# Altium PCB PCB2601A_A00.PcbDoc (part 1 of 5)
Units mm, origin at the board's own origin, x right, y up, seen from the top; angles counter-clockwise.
Board outline 30.4 x 51 mm, 8 copper layers (Top Layer, Signal Layer 2, Signal Layer 3, Signal Layer 4, Signal Layer 5, Signal Layer 6, Signal Layer 7, Bottom Layer), stack 1.492 mm thick; 194 components, 130 nets, 5039 pads, 478 vias.
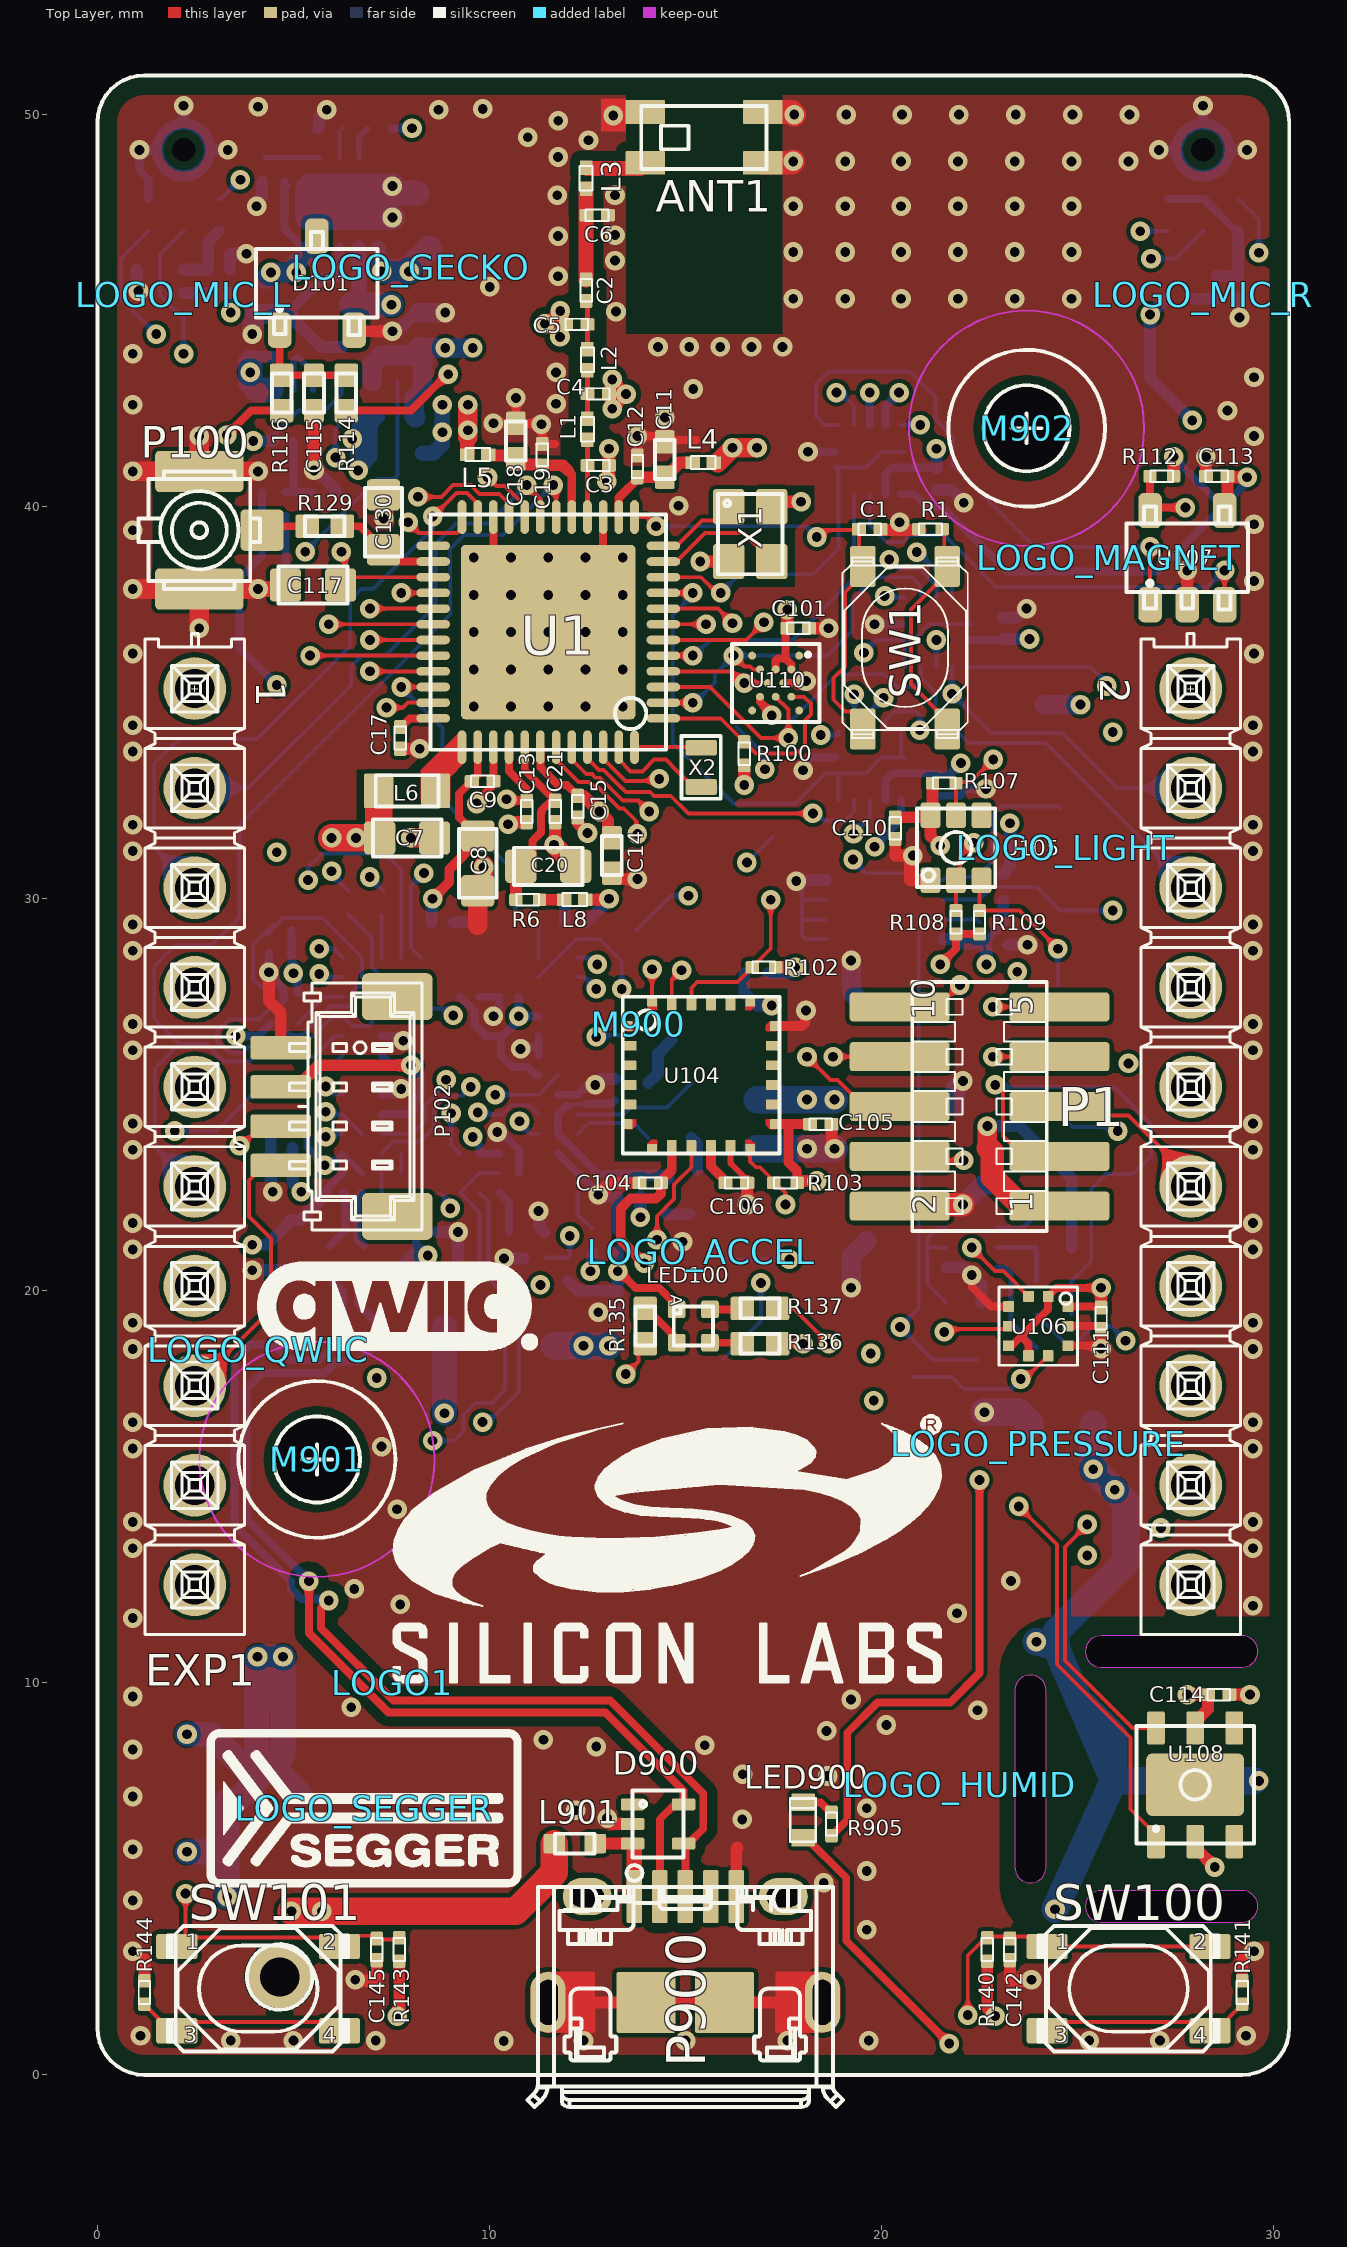
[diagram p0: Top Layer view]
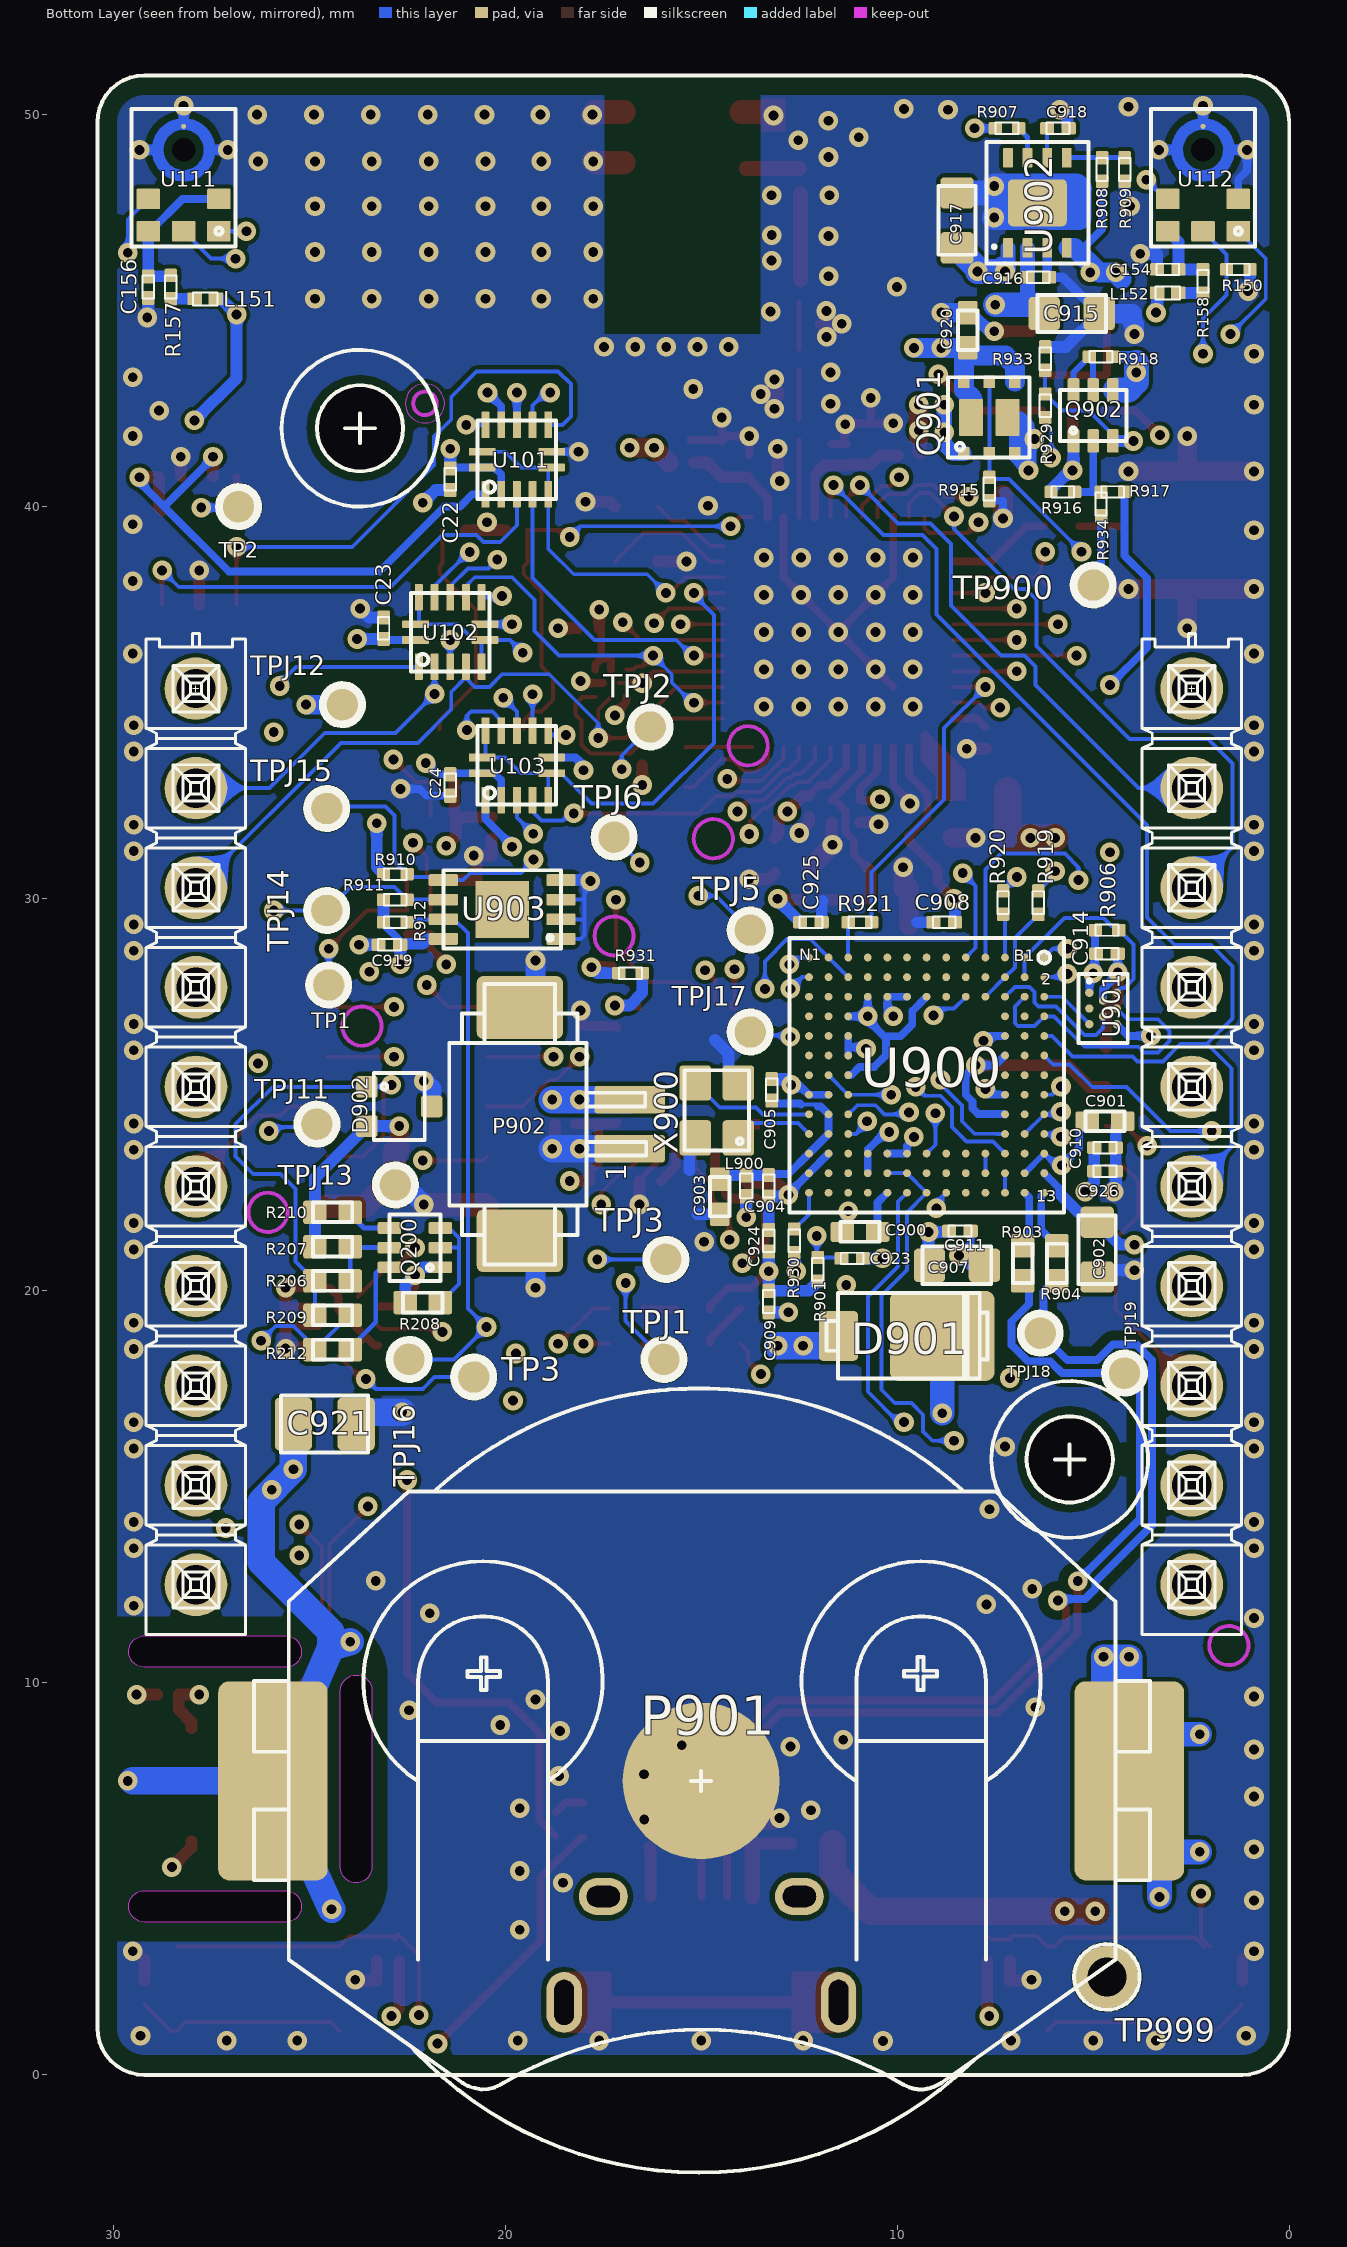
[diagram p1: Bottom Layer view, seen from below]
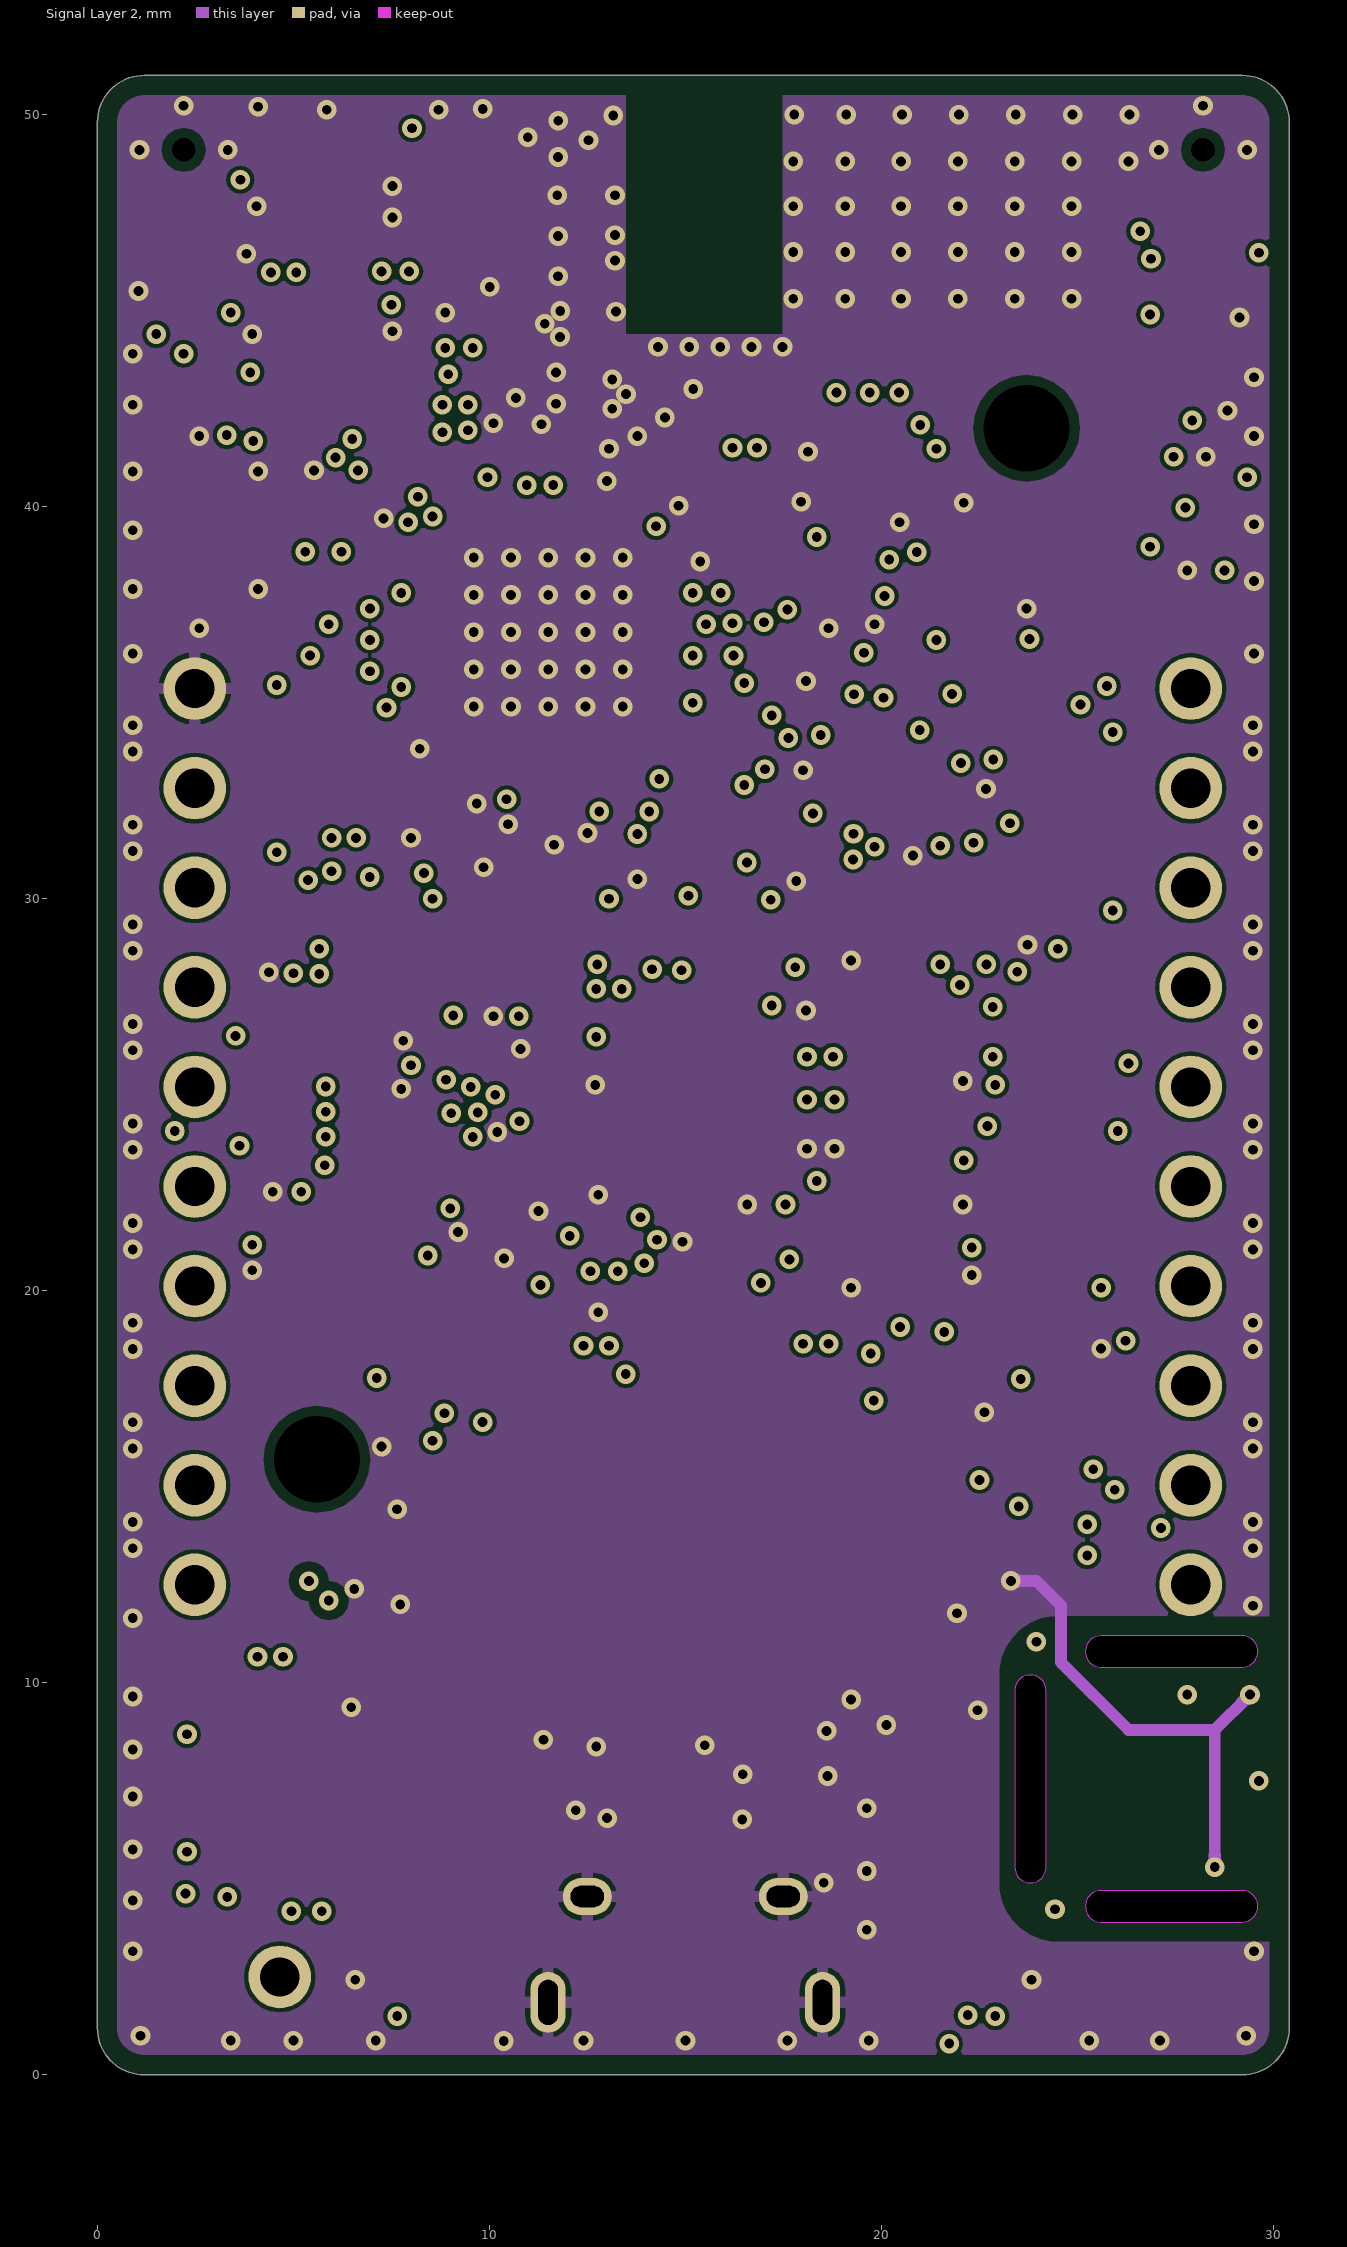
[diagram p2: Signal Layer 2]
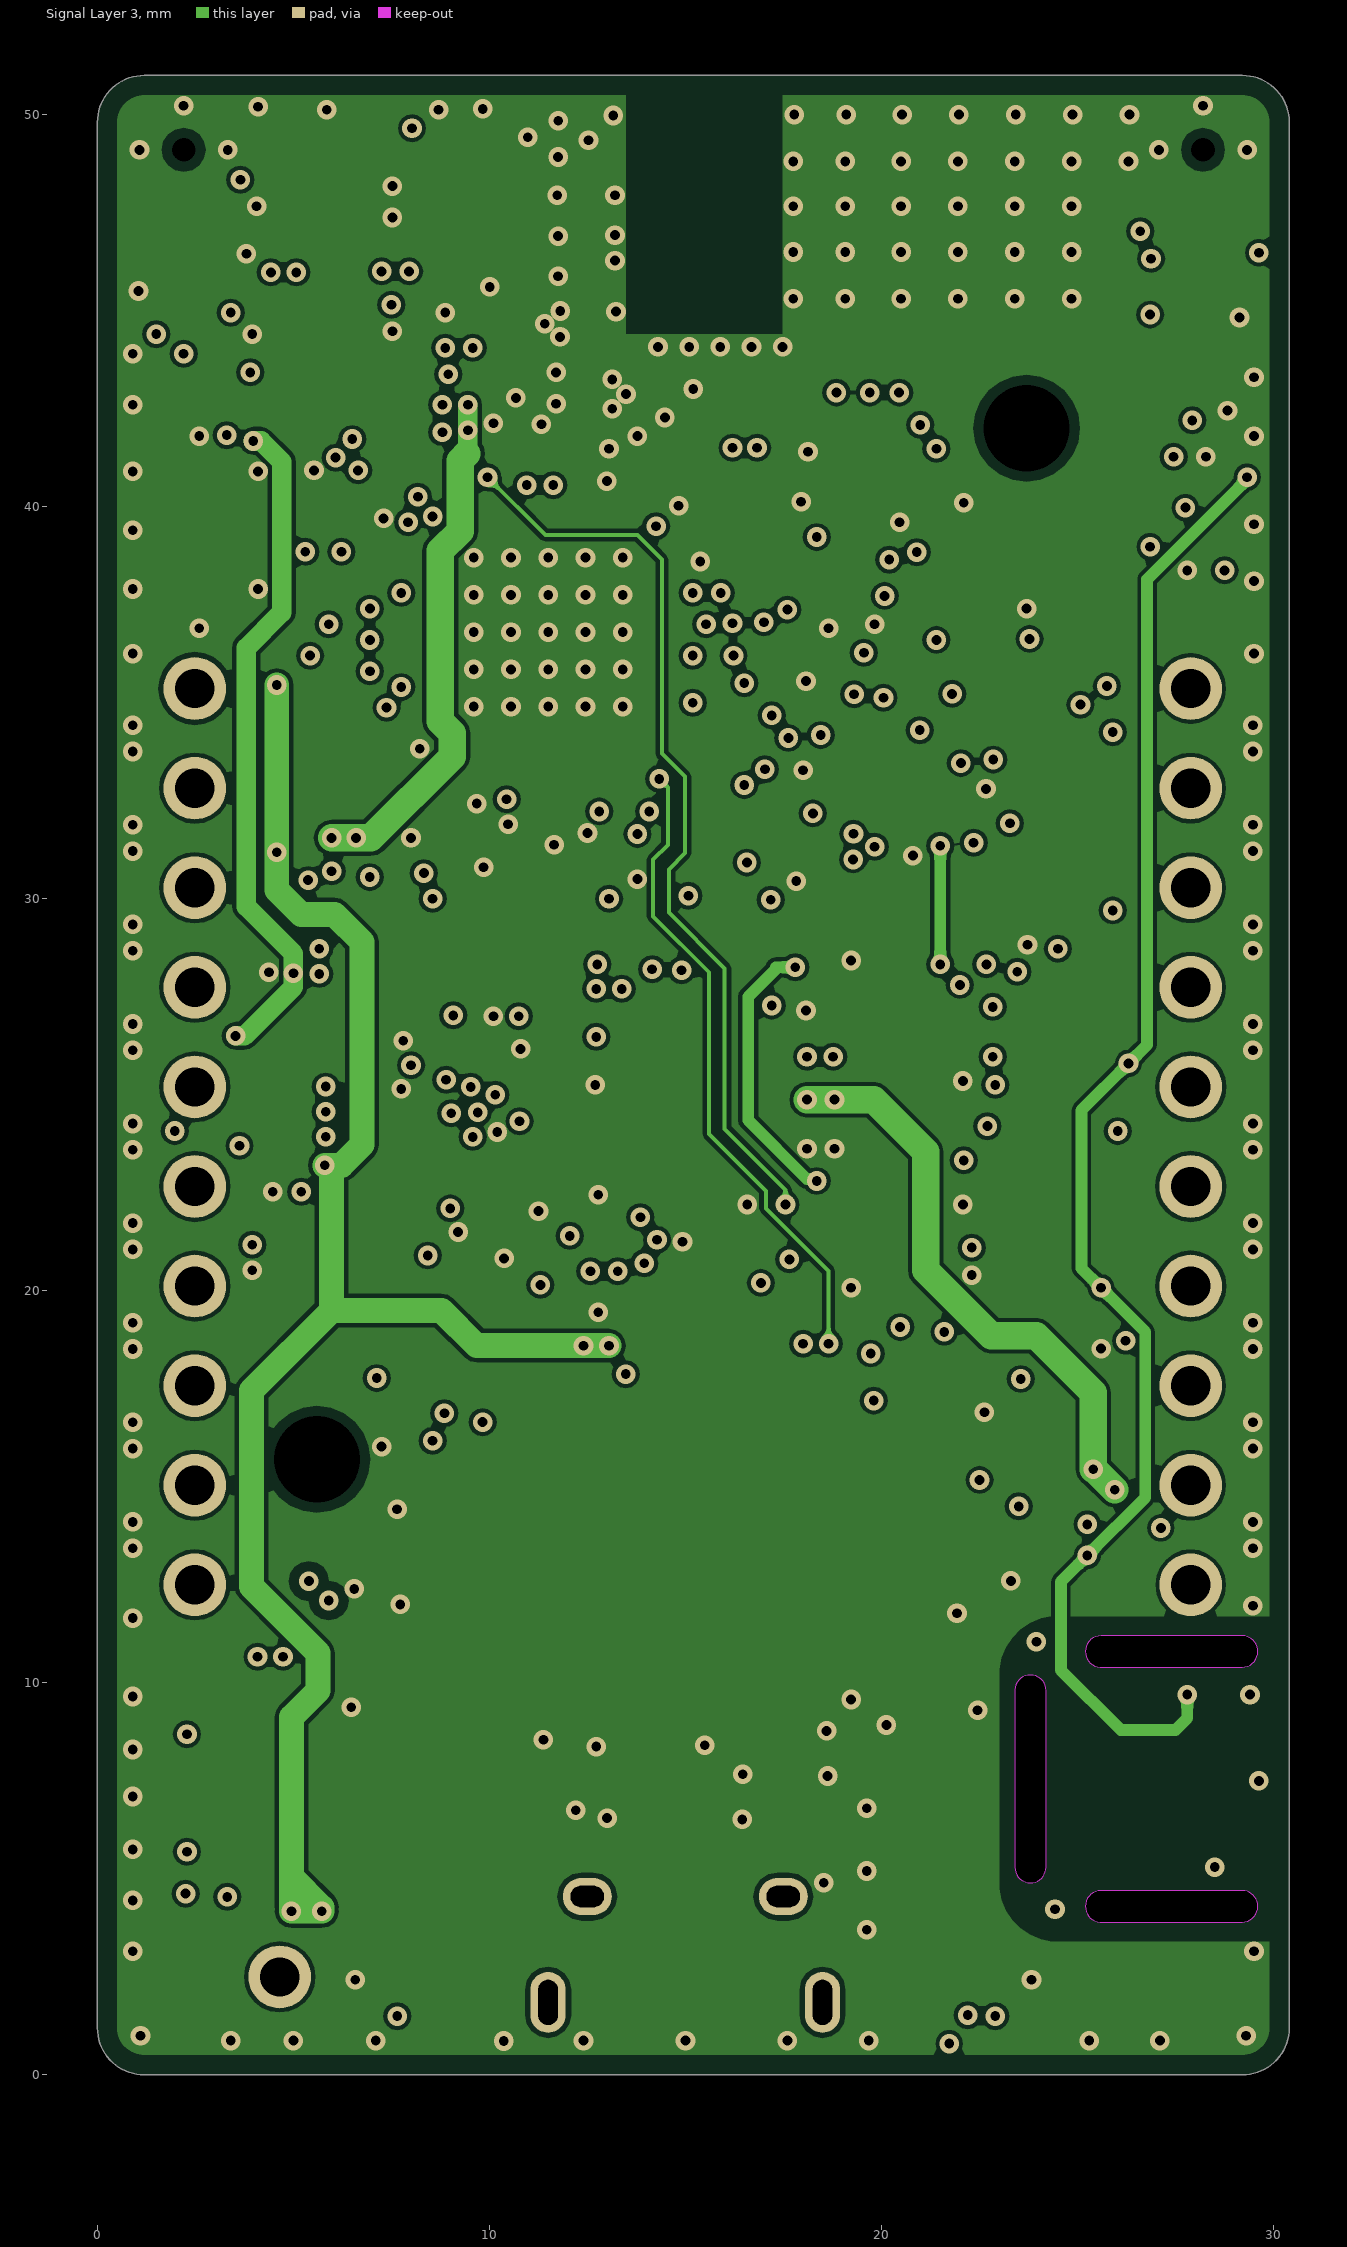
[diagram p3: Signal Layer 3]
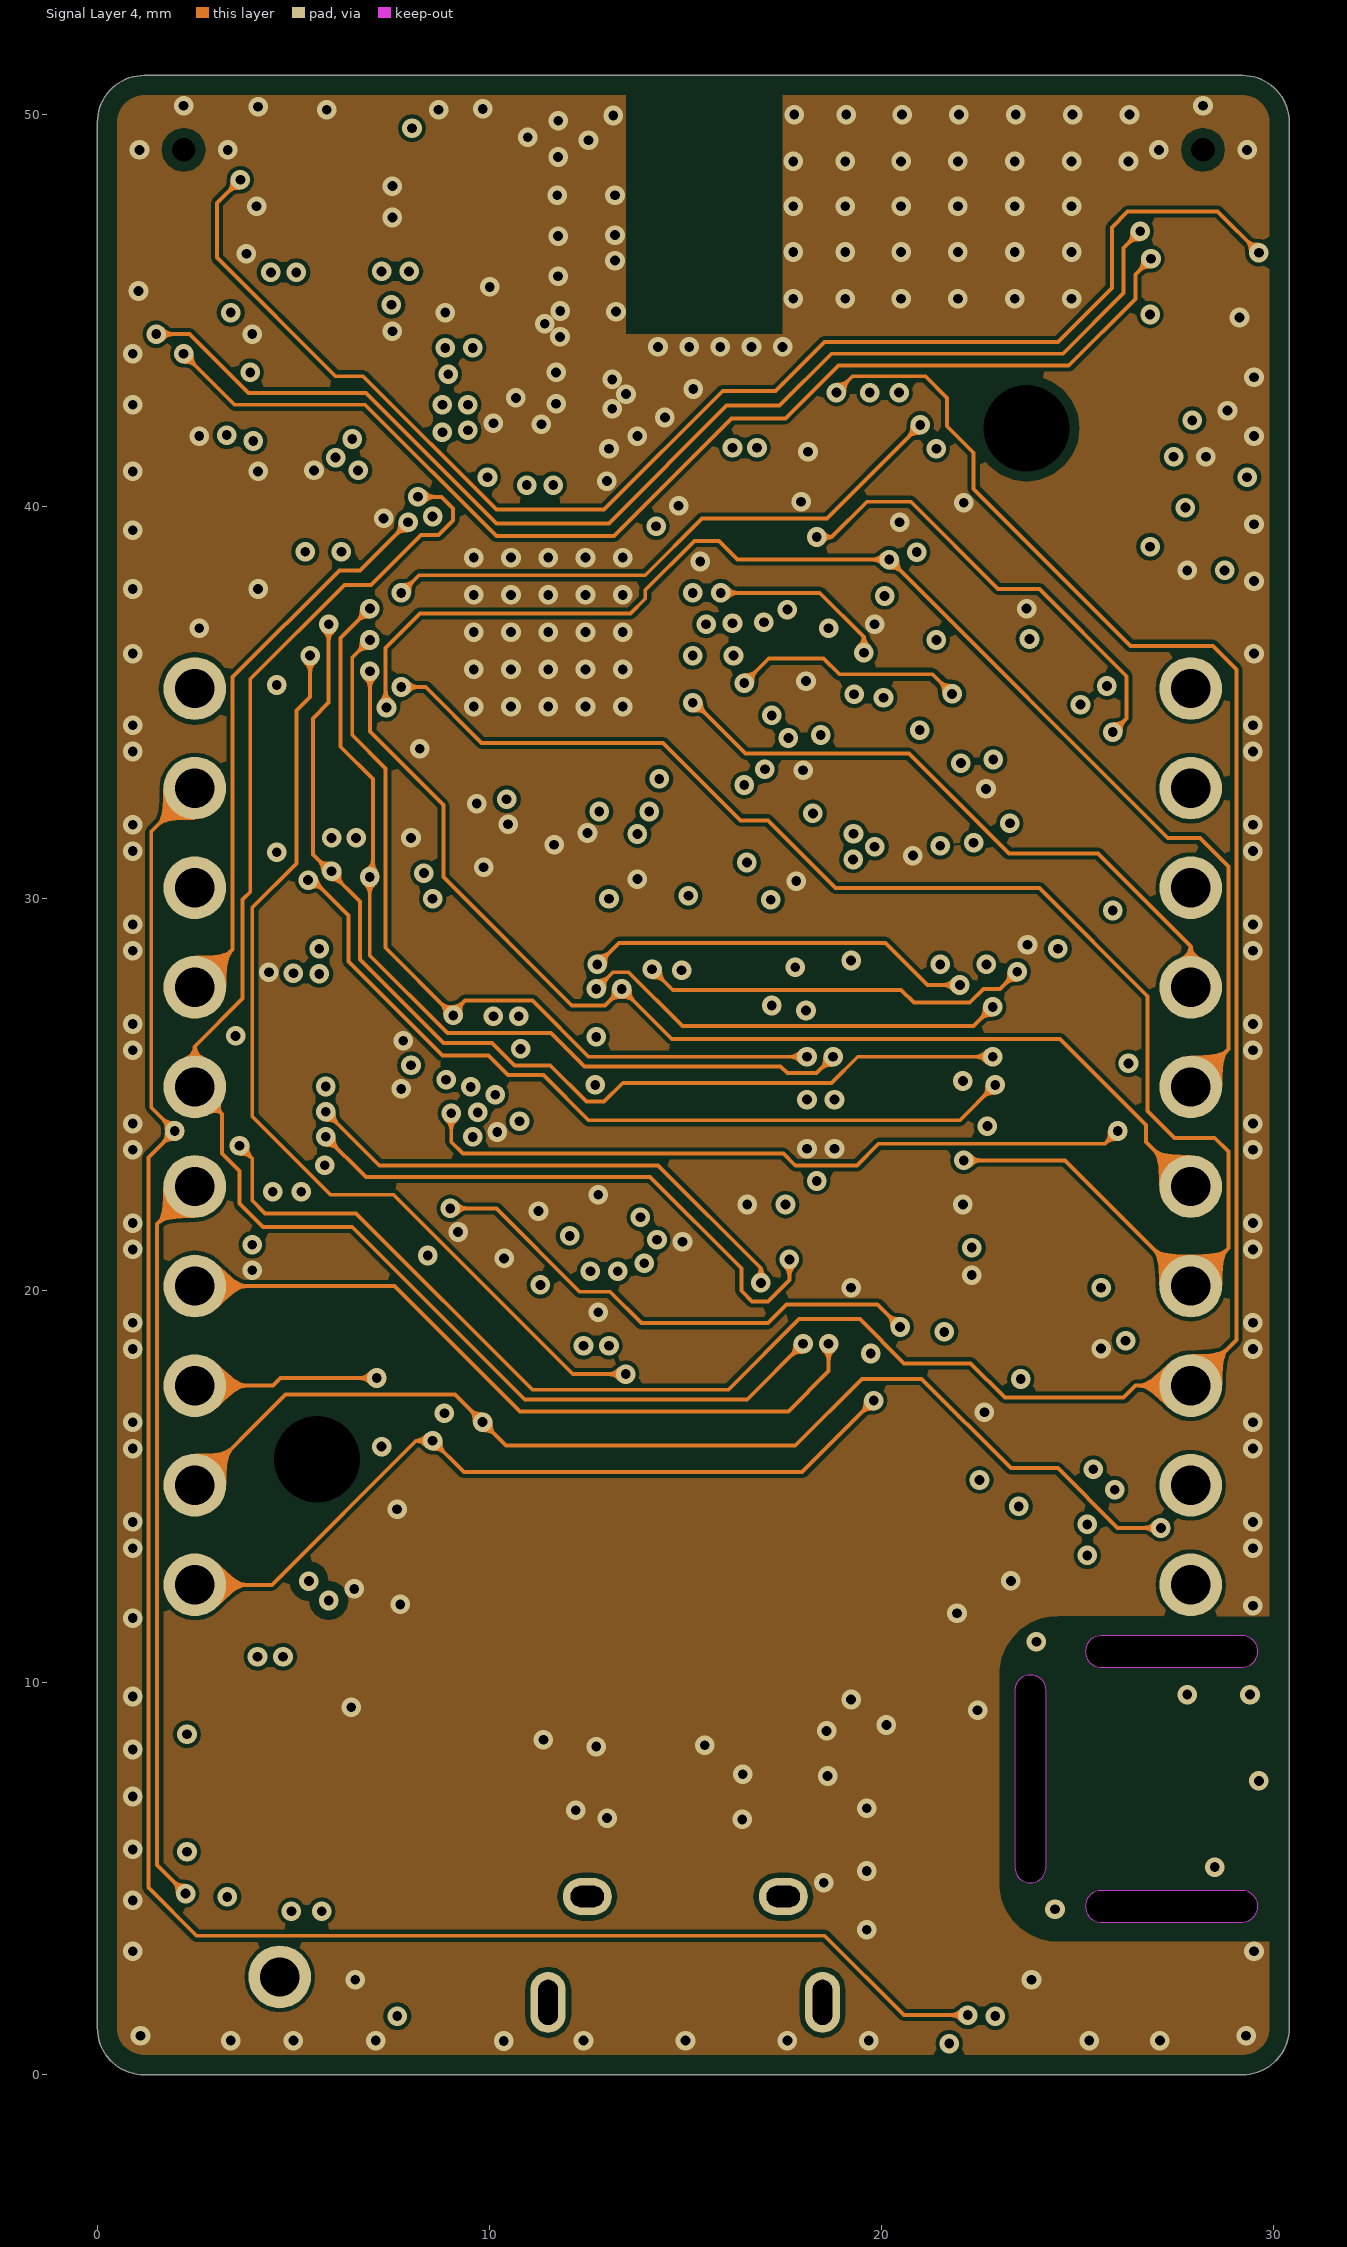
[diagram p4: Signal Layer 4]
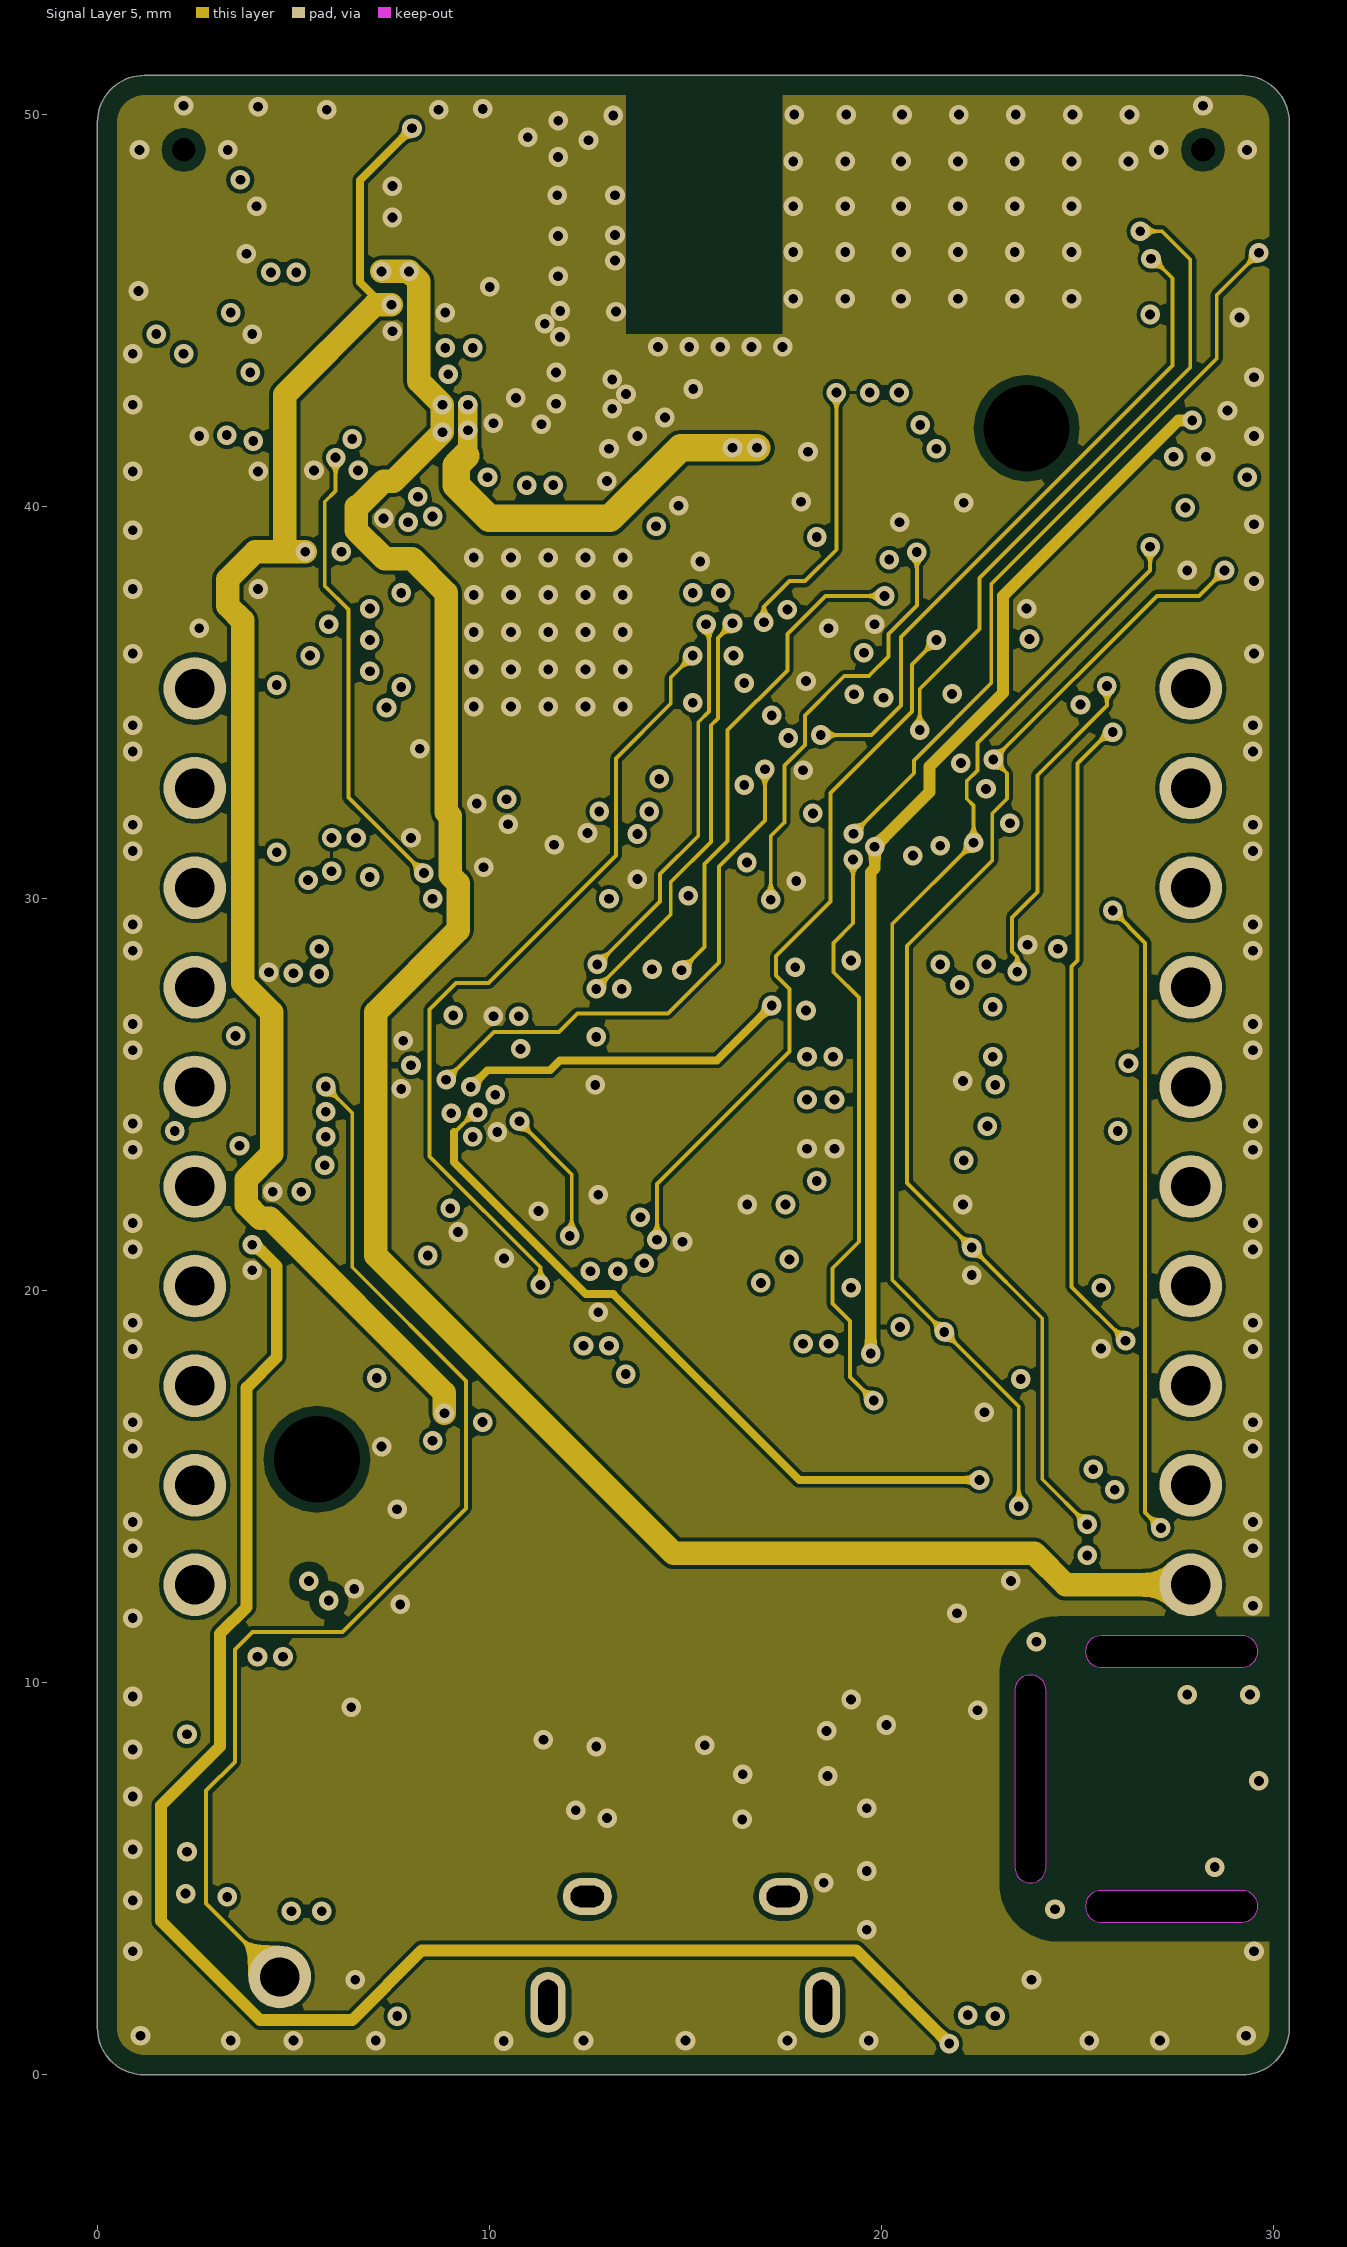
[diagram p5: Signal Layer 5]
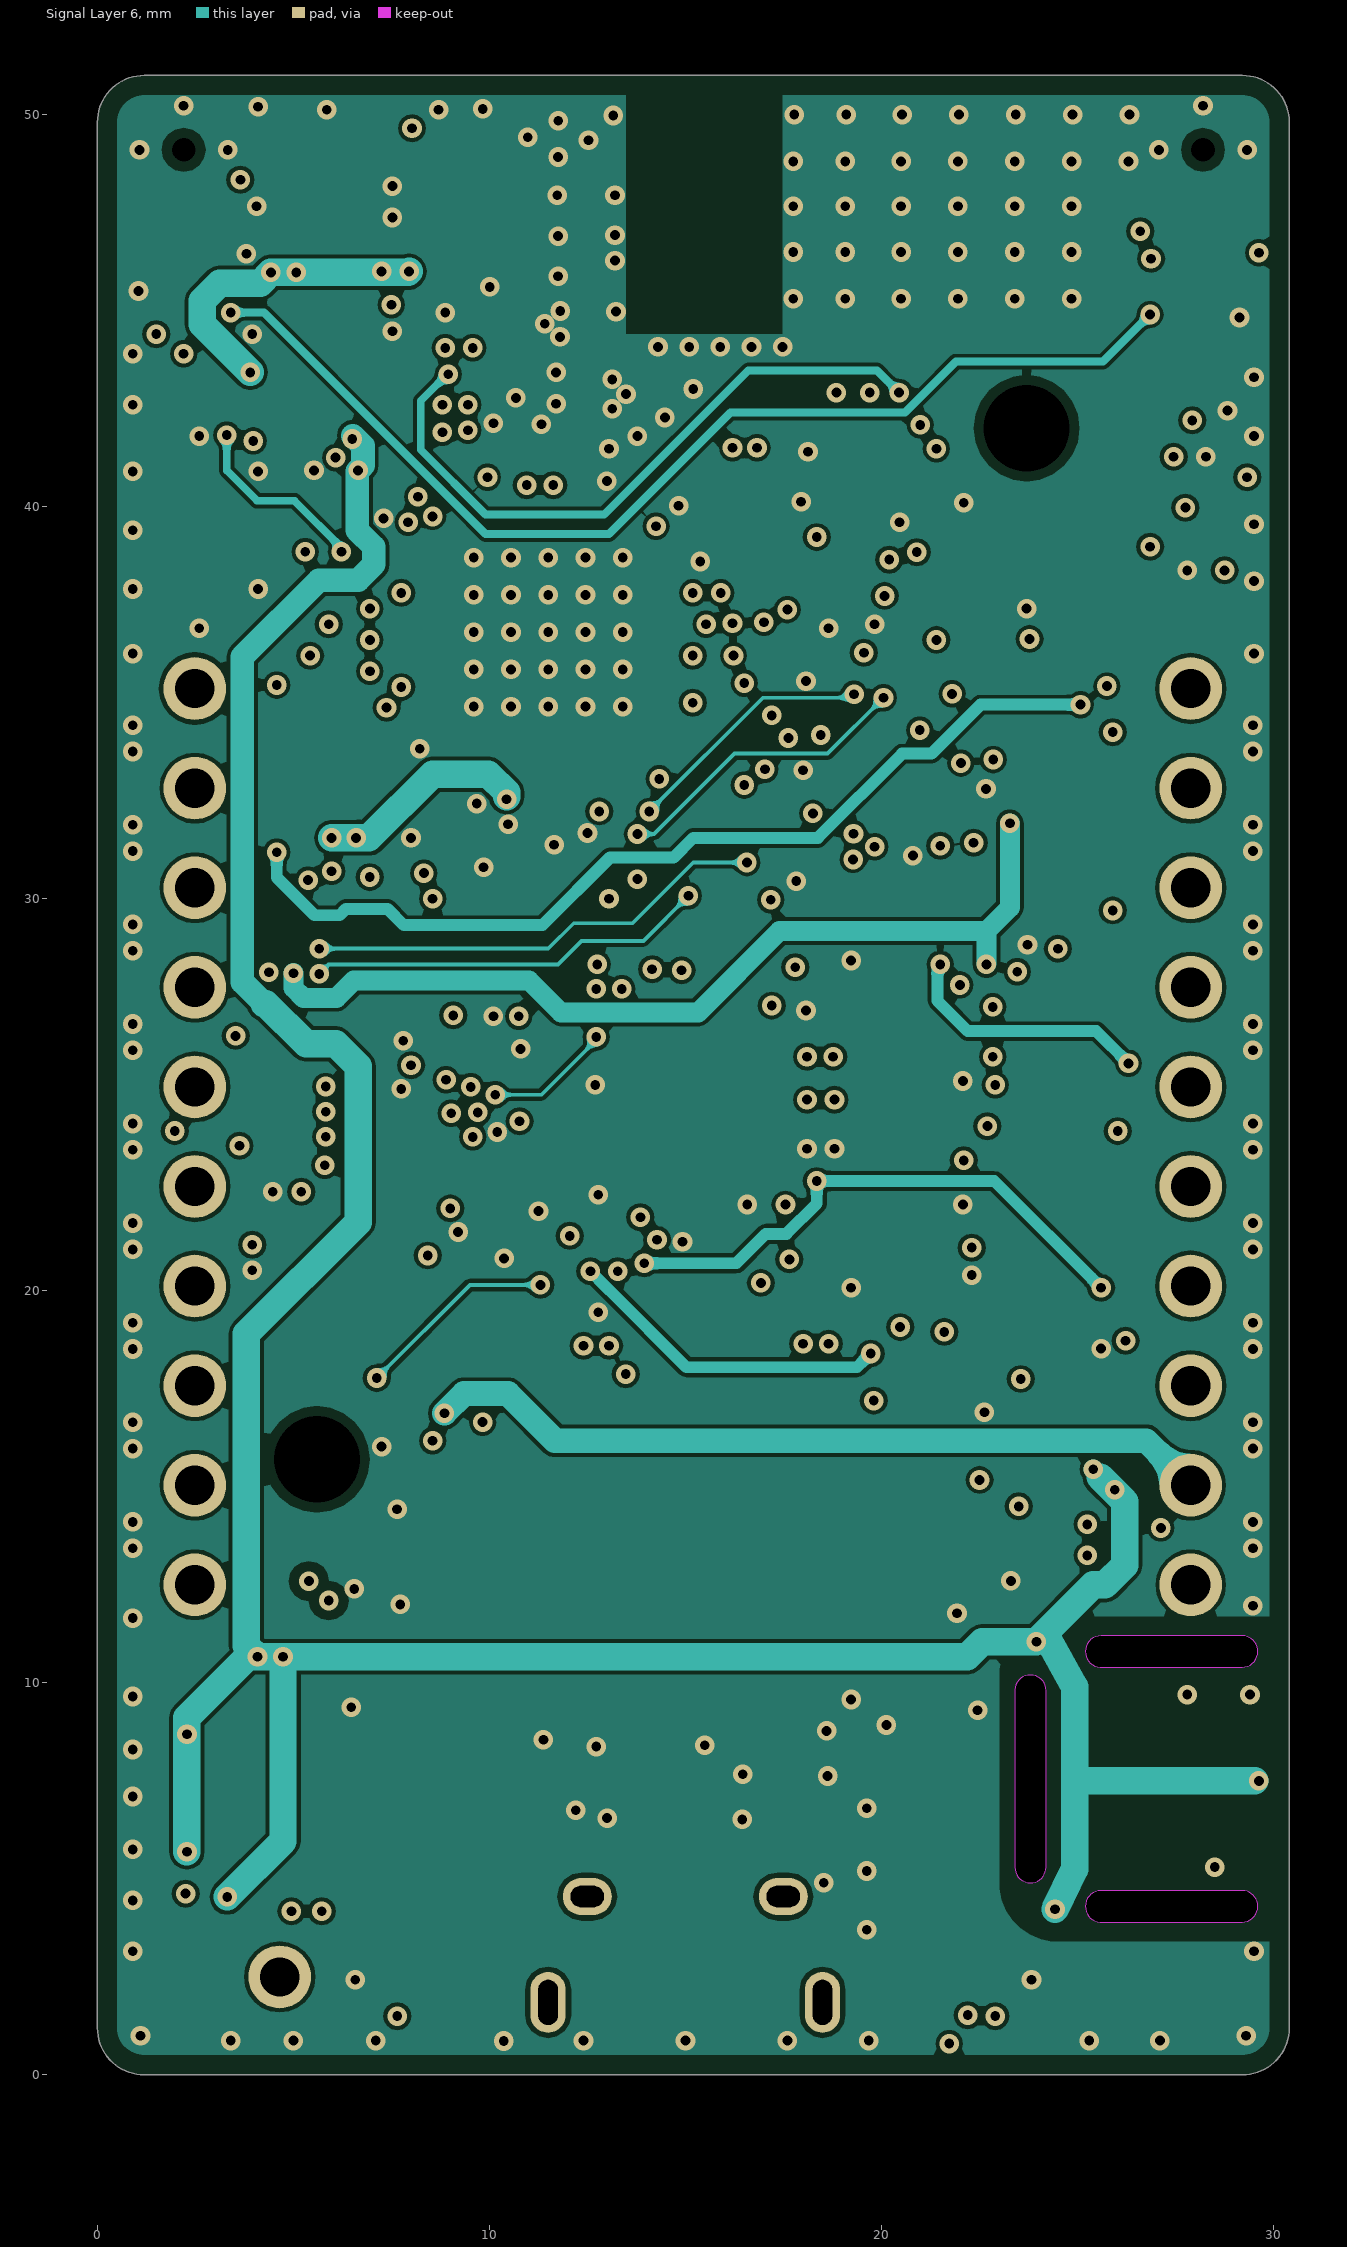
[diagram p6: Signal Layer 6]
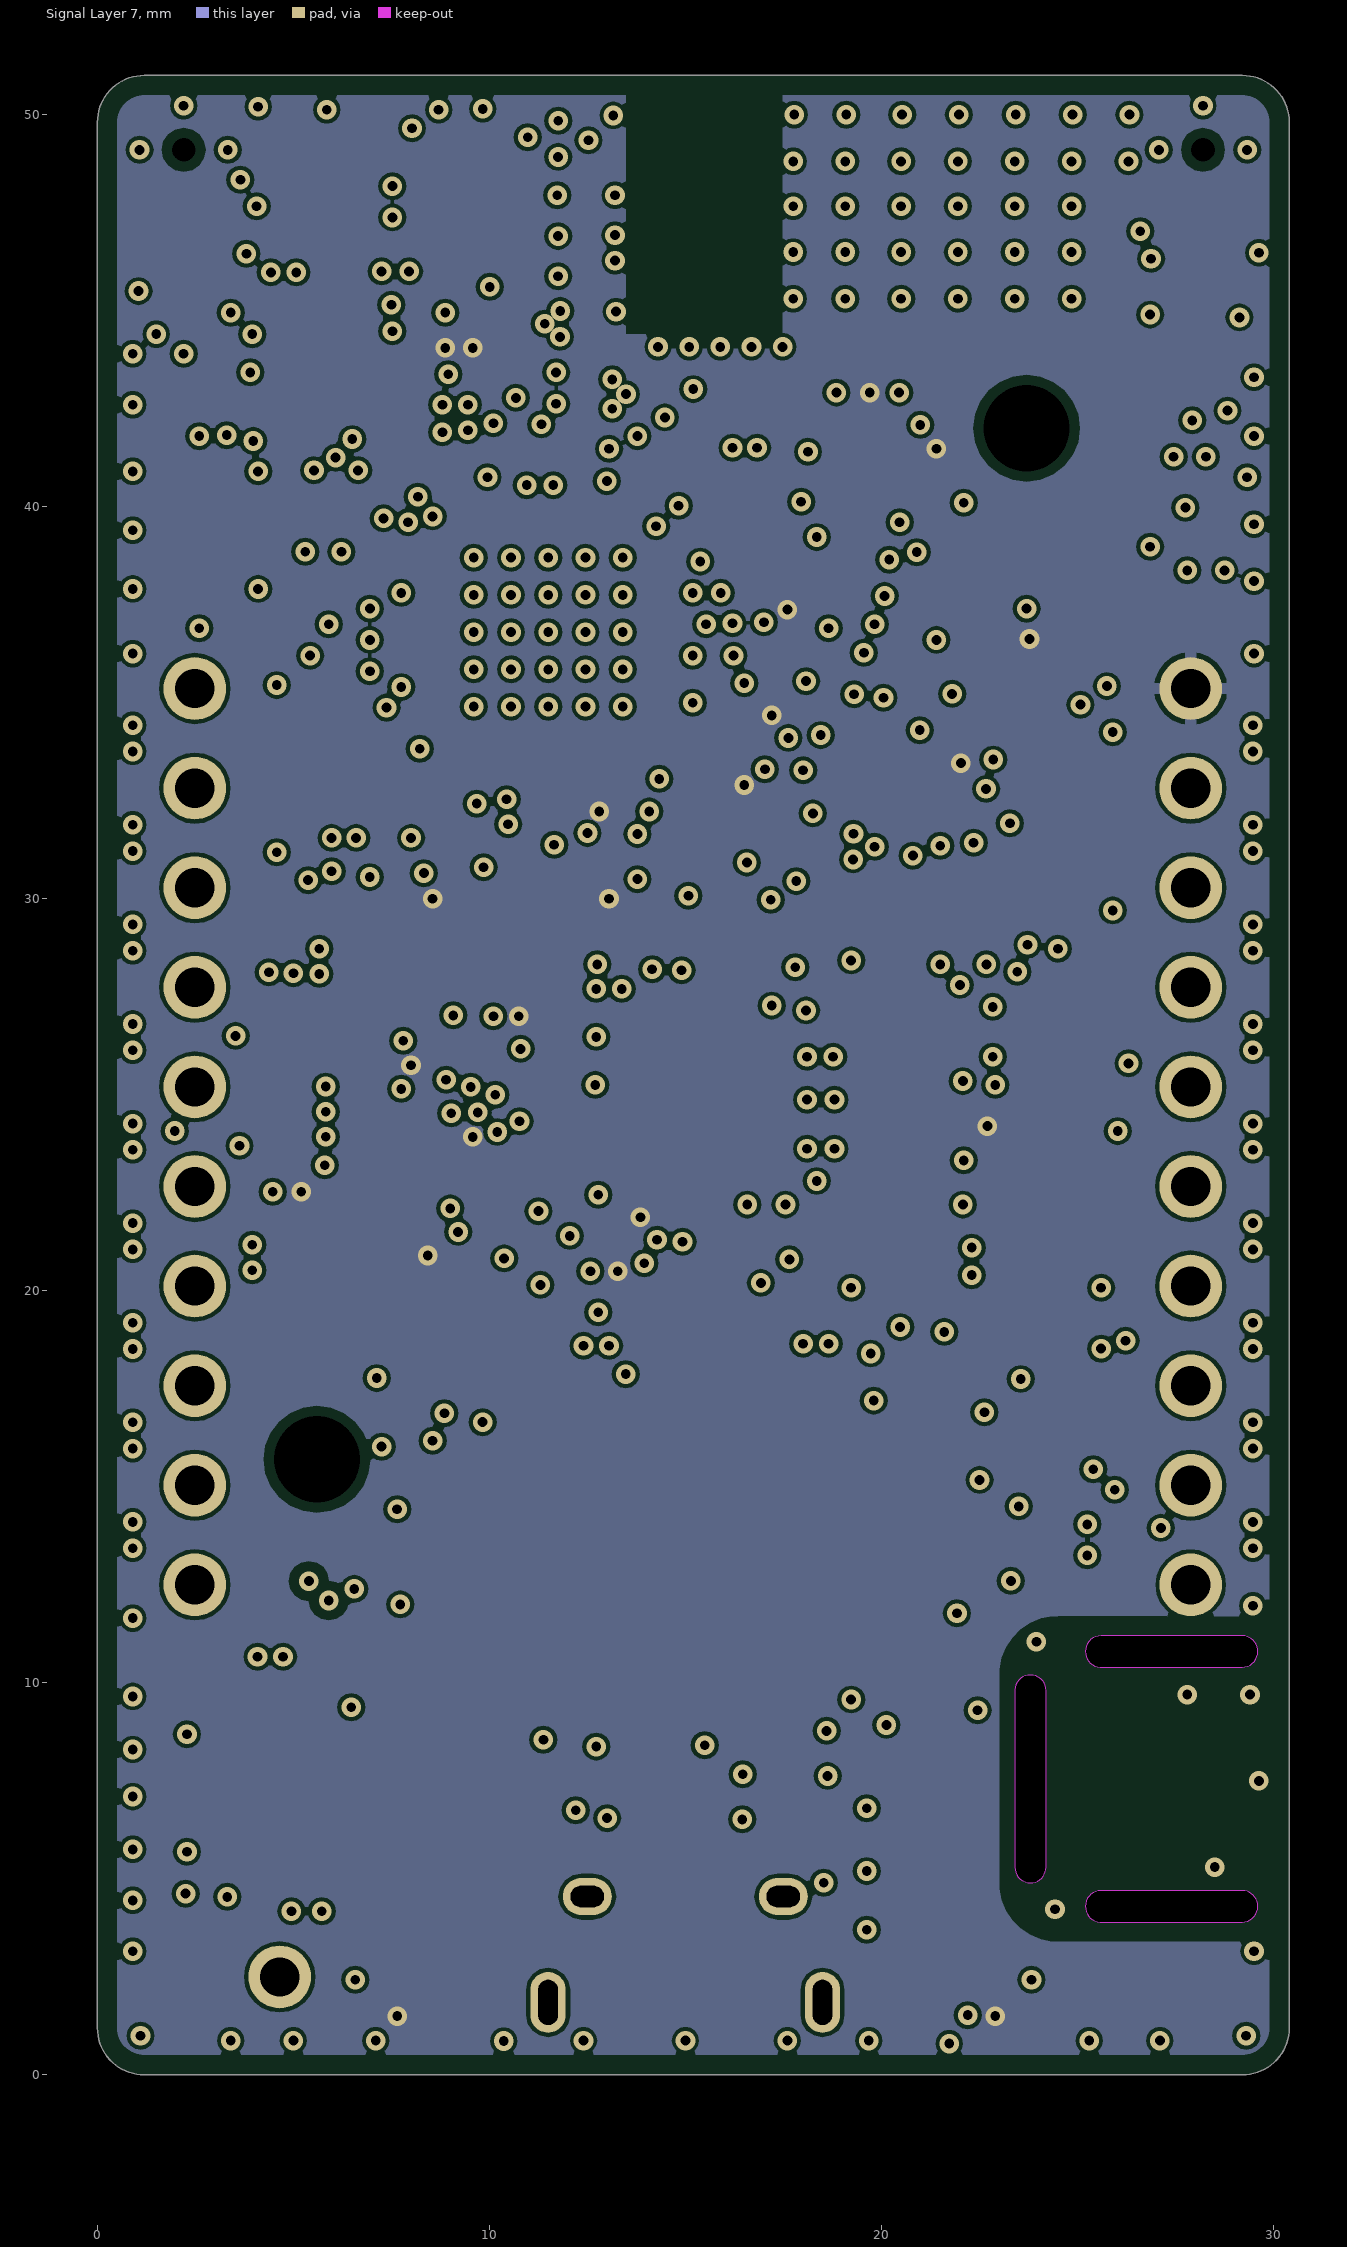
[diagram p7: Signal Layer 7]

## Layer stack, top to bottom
Top Solder: solder mask 0.05, Solder Resist, Dk 3.5
Top Layer: signal copper 0.038
Dielectric 1: core 0.304, FR-4, Dk 4.2
Signal Layer 2: signal copper 0.018
Dielectric 2: prepreg 0.1, FR-4, Dk 4.2
Signal Layer 3: signal copper 0.018
Dielectric 3: core 0.1, FR-4, Dk 4.2
Signal Layer 4: signal copper 0.018
Dielectric 4: prepreg 0.3, FR-4, Dk 4.2
Signal Layer 5: signal copper 0.018
Dielectric 5: core 0.1, FR-4, Dk 4.2
Signal Layer 6: signal copper 0.018
Dielectric 6: prepreg 0.1, FR-4, Dk 4.2
Signal Layer 7: signal copper 0.018
Dielectric  7: core 0.304, FR-4, Dk 4.2
Bottom Layer: signal copper 0.038
Bottom Solder: solder mask 0.05, Solder Resist, Dk 3.5

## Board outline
0,1.2 0,49.8 cw(c1.2,49.8) 1.2,51 29.2,51 cw(c29.2,49.8) 30.4,49.8 30.4,1.2 cw(c29.2,1.2) 29.2,0 1.2,0 cw(c1.2,1.2)
cut-out: 25.2,4.3 ccw(c25.588,4.288) 25.575,3.9 29.2,3.9 ccw(c29.2,4.3) 29.6,4.3 ccw(c29.2,4.3) 29.2,4.7 25.6,4.7 ccw(c25.6,4.3)
cut-out: 23.4,5.3 ccw(c23.8,5.3) 23.8,4.9 ccw(c23.8,5.3) 24.2,5.3 24.2,9.8 ccw(c23.8,9.8) 23.8,10.2 ccw(c23.788,9.812) 23.4,9.825
cut-out: 25.2,10.8 ccw(c25.588,10.788) 25.575,10.4 29.2,10.4 ccw(c29.2,10.8) 29.6,10.8 ccw(c29.2,10.8) 29.2,11.2 25.6,11.2 ccw(c25.6,10.8)

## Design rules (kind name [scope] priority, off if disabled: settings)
AcuteAngle [All] p1: minimum=5.00000000000000E+0001 checktracksonly=FALSE
BoardOutlineClearance BoardOutlineClearance_IGNORE_Silk [OnSilkscreen] p1: gap=0 ignorepadtopadclearanceinfootprint=FALSE
BoardOutlineClearance [All] p2: gap=0.5 ignorepadtopadclearanceinfootprint=FALSE except(0.25: Arc-CutoutEdge Track-CutoutEdge SMDPad-CutoutEdge THPad-CutoutEdge Via-CutoutEdge Fill-CutoutEdge Poly-CutoutEdge Region-CutoutEdge Text-CutoutEdge)
Clearance Clearance_RF [InNetClass('RF') vs InPolygon] p1: gap=0.25 ignorepadtopadclearanceinfootprint=FALSE
Clearance Clearance_USB [InNetClass('USB') vs InPolygon] p2: gap=0.25 ignorepadtopadclearanceinfootprint=FALSE
Clearance USB_LINE [InNet('DBGMCU_USB_DM') vs InNet('DBGMCU_USB_DP')] p3: gap=0.127 ignorepadtopadclearanceinfootprint=FALSE except(0: Arc-Hole Track-Hole SMDPad-Hole THPad-Hole Via-Hole Fill-Hole Poly-Hole Region-Hole Text-Hole)
Clearance Clearance_NPL_Mic [((ObjectKind = 'Pad') And (Layer = 'MultiLayer') And (PadIsPlated = 'False')) and HasFootprint('MIC_INVENSENSE_ICS-43434') vs OnLayer('Bottom Layer')] p4: gap=0.2 ignorepadtopadclearanceinfootprint=FALSE
Clearance Clearance_NPL [(ObjectKind = 'Pad') And (Layer = 'MultiLayer') And (PadIsPlated = 'False')] p5: gap=0.25 ignorepadtopadclearanceinfootprint=FALSE
Clearance Clearance_General [All] p6: gap=0.1 ignorepadtopadclearanceinfootprint=FALSE
ComponentClearance [All] p1: gap=0 collisioncheckmode=3 verticalgap=0 showdistances=FALSE
DiffPairsRouting [All] p1: maxlimit=0.127 minlimit=0.102 mostfreqgap=0.127 toplayer_maxgap=0.102 toplayer_prefgap=0.102 toplayer_minwidth=0.203 toplayer_maxwidth=0.203 toplayer_prefwidth=0.203 midlayer1_mingap=0.127 midlayer1_minwidth=0.099 midlayer1_maxwidth=0.099 midlayer1_prefwidth=0.099 midlayer2_mingap=0.127 midlayer2_minwidth=0.079 midlayer2_maxwidth=0.079 midlayer2_prefwidth=0.079 midlayer3_mingap=0.127 midlayer3_minwidth=0.099 midlayer3_maxwidth=0.099 midlayer3_prefwidth=0.099 midlayer4_mingap=0.127 midlayer4_minwidth=0.099 midlayer4_maxwidth=0.099 midlayer4_prefwidth=0.099 midlayer5_mingap=0.127 midlayer5_minwidth=0.099 midlayer5_maxwidth=0.099 midlayer5_prefwidth=0.099 midlayer6_mingap=0.127 midlayer6_minwidth=0.079 midlayer6_maxwidth=0.079 midlayer6_prefwidth=0.079 bottomlayer_maxgap=0.102 bottomlayer_prefgap=0.102 bottomlayer_minwidth=0.203 bottomlayer_maxwidth=0.203 bottomlayer_prefwidth=0.203 impedanceprofiledriven=TRUE impedanceprofileid={763DEC86-5979-4838-BC09-05E4C349F8E1} impedanceprofilevalue=90.000000 maxuncoupledlength=12.7
HoleToHoleClearance HoleToHoleClearance_ANT1toPAD [Incomponent ('ANT1') vs ISpad] p1: gap=0 allowstackedmicrovias=TRUE
HoleToHoleClearance HoleToHoleClearance_P5toSW4 [Incomponent ('P5') vs Incomponent ('SW4')] p2: gap=0 allowstackedmicrovias=TRUE
HoleToHoleClearance HoleToHoleClearance_R1toR2 [Incomponent ('R1') vs Incomponent ('R2')] p3: gap=0 allowstackedmicrovias=TRUE
HoleToHoleClearance HoleToHoleClearance_general [All] p4: gap=0.375 allowstackedmicrovias=TRUE
MinimumSolderMaskSliver MinimumSolderMaskSliver_IGNORE_BGA8 [HasFootprint('BGA8_M040_1.24x1.75_WLCSP') vs HasFootprint('BGA8_M040_1.24x1.75_WLCSP')] p1: minsoldermaskwidth=0
MinimumSolderMaskSliver [not HasFootprint('LOGO*') vs not HasFootprint('LOGO*')] p2: minsoldermaskwidth=0.152
PolygonConnect PolygonConnect_PAD_DROWN [InComponentClass('POLYGON_DROWN')] p1: connectstyle=Direct reliefconductorwidth=0.254 reliefentries=4 polygonreliefangle="90 Angle" airgapwidth=0.254
PolygonConnect PolygonConnect_Throughhole_GND [IsThruPin vs InNet('GND') and not OnLayer('Signal Layer 2')] p2: connectstyle=NoConnect reliefconductorwidth=0.254 reliefentries=4 polygonreliefangle="90 Angle" airgapwidth=0.125
PolygonConnect PolygonConnect_general [All] p3: thpad.connectstyle=Relief thpad.reliefconductorwidth=0.3 thpad.reliefentries=4 thpad.polygonreliefangle="90 Angle" thpad.airgapwidth=0.125 smdpad.connectstyle=NoConnect smdpad.reliefconductorwidth=0.33 smdpad.reliefentries=4 smdpad.polygonreliefangle="90 Angle" smdpad.airgapwidth=0.102 via.connectstyle=Direct via.reliefconductorwidth=0.33 via.reliefentries=4 via.polygonreliefangle="90 Angle" via.airgapwidth=0.127
RoutingVias [All] p1: holewidth=0.25 width=0.508 viastyle="Through Hole" minholewidth=0.25 minwidth=0.508 maxholewidth=1 maxwidth=1.5 useviatemplates=TRUE viatemplateguid#1={3A37D5D4-6EF9-41F7-AE12-89C7EBFE3D30} viatemplatename#1=v50h25m0mx0
ShortCircuit ShortCircuit_ANTtoPAD [InNet('NetAT1_1') vs InNet('GND')] p1: allowed=TRUE
ShortCircuit ShortCircuit_General [All] p2: allowed=FALSE
SilkToSilkClearance [All] p1: silktosilkclearance=0.102
SilkToSolderMaskClearance [IsPad] p1: minsilkscreentomaskgap=0.102 clearancetoexposedcopper=TRUE
SolderMaskExpansion [All] p1: expansion=0.05 istentingtop=FALSE
UnRoutedNet [All] p1: checkbadconnections=TRUE
Width [All] p1: maxlimit=5.08 minlimit=0.1 preferedwidth=0.1
22 further rules are at their usual default settings.

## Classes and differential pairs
component class POLYGON_DROWN: ANT1 C6 C11 C12 C18 C19 P901
net class USB: DBG_USB_DM DBG_USB_DP
net class RF: N17344672 N17345163
differential pair USB: +DBG_USB_DP -DBG_USB_DM

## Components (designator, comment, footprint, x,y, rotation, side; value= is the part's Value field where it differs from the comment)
ANT1 "2450AT18D0100" ANT_JOH_2450AT18D0100 15.472,49.416 r0 top
C1 "100N" C0201_L 19.7,39.425 r0 top
C2 "18P" C0201_L 12.467,45.522 r90 top
C3 "1P8" C0201_L 12.775,41.05 r0 top
C4 "1P3" C0201_L 12.775,42.875 r0 top
C5 "TBD" C0201_L 12.228,44.647 r180 top
C6 "1P5" C0201_L 12.746,47.435 r0 top
C7 "4U7" C0603_L 7.9,31.55 r0 top
C8 "10U" C0603_L 9.7,30.9 r270 top
C9 "100N" C0201_L 9.825,33 r0 top
C11 "2U2" C0402_L 14.475,41.2 r90 top
C12 "18P" C0201_L 13.775,41.025 r90 top
C13 "100N" C0201_L 10.95,32.225 r270 top
C14 "1U" C0402_L 13.125,31.1 r270 top
C15 "100N" C0201_L 12.25,32.35 r270 top
C17 "2U2" C0201_L 7.725,34.1 r270 top
C18 "1U" C0402_L 10.675,41.675 r90 top
C19 "120P" C0201_L 11.35,41.325 r90 top
C20 "10U" C0603_L 11.5,30.825 r0 top
C21 "10N" C0201_L 11.675,32.225 r270 top
C22 "100N" C0201_L 21.4,40.7 r270 bottom
C23 "100N" C0201_L 23.1,36.9 r90 bottom
C24 "100N" C0201_L 21.4,32.9 r270 bottom
C101 "100N" C0201_L 17.875,36.9 r0 top
C104 "2U2" C0201_L 14.1,22.75 r180 top
C105 "100N" C0201_L 18.45,24.25 r0 top
C106 "470N" C0201_L 16.3,22.75 r0 top
C110 "100N" C0201_L 20.35,31.8 r270 top
C111 "100N" C0201_L 25.6,19.3 r270 top
C113 "100N" C0201_L 28.55,40.775 r180 top
C114 "100N" C0201_L 28.6,9.7 r0 top
C115 "1U" C0402_L 5.525,42.9 r270 top
C117 "10U" C0603_L 5.5,38 r180 top
C130 "10N" C0603_L 7.3,39.6 r90 top
C142 "1N" C0201_L 23.275,3.2 r270 top
C145 "1N" C0201_L 7.125,3.2 r270 top
C154 "1U" C0201_L 3.1,46.05 r0 bottom
C156 "1U" C0201_L 29.1,45.6 r270 bottom
C900 "1U" C0402_L 10.95,21.5 r0 bottom
C901 "1U" C0402_L 4.7,24.325 r180 bottom
C902 "4U7" C0603_L 4.9,21.05 r270 bottom
C903 "1U" C0402_L 14.525,22.4 r270 bottom
C904 "10N" C0201_L 13.275,22.675 r270 bottom
C905 "10N" C0201_L 13.2,25.125 r90 bottom
C907 "4U7" C0603_L 8.475,20.65 r0 bottom
C908 "100N" C0201_L 8.8,29.4 r0 bottom
C909 "100N" C0201_L 13.275,19.725 r270 bottom
C910 "100N" C0201_L 4.7,23.65 r180 bottom
C911 "100N" C0201_L 8.4,21.525 r0 bottom
C914 "100N" C0201_L 4.65,28.6 r180 bottom
C915 "4U7" C0603_L 5.55,44.925 r180 bottom
C916 "100N" C0201_L 6.4,45.85 r180 bottom
C917 "10U" C0603_L 8.475,47.3 r90 bottom
C918 "33N" C0201_L 5.9,49.65 r180 bottom
C919 "100N" C0201_L 22.95,28.825 r0 bottom
C920 "1U" C0402_L 8.2,44.5 r90 bottom
C921 "47U" C0805_L 24.6,16.6 r180 bottom
C923 "100N" C0201_L 11.15,20.825 r180 bottom
C924 "100N" C0201_L 13.275,21.275 r90 bottom
C925 "100N" C0201_L 12.2,29.4 r180 bottom
C926 "100N" C0201_L 4.7,23.05 r180 bottom
D101 "ADR1581" SOT23_123_L 5.6,45.7 r90 top
D900 "SP1001-04" SOT553_L 14.3,6.4 r0 top
D901 "SS3P3" DO220AA 9.7,18.85 r0 bottom
D902 "ESD" SOT663_NXP 22.7,24.7 r180 bottom
EXP1 "HEADER_2X10_2.54MM_TH_SPLIT" HDR_M254-1X10_PLUS_1X10_NO_3D 27.886,35.36 r270 top locked
L1 "2N2" COIL_0201_L 12.5,41.975 r90 top
L2 "20P" COIL_0201_L 12.5,43.75 r90 top
L3 "1N5" COIL_0201_L 12.467,48.375 r90 top
L4 "BLM03AG700SN1D" COIL_MUR_BLM03_0201 15.45,41.125 r180 top
L5 "BLM03AG700SN1D" COIL_MUR_BLM03_0201 9.7,41.325 r0 top
L6 "2U2" COIL_0603_L 7.9,32.75 r180 top
L8 "742692004" COIL_0201_L 12.175,29.975 r180 top
L151 "742692004" COIL_0201_L 27.65,45.3 r0 bottom
L152 "742692004" COIL_0201_L 3.1,45.45 r180 bottom
L900 "742692004" COIL_0201_L 13.85,22.675 r90 bottom
L901 "782422221" COIL_0402_L 12.175,5.9 r180 top
LED100 "RGB" LED_LUMEX_SML-LX0404-4 15.2,19.1 r270 top
LED900 "BLUE" LED_0402_CAT2 18,6.5 r90 top
LOGO1 "Comment" LOGO_SILABS_W14.0 7.525,10 r0 top locked
LOGO_ACCEL "Comment" LOGO_ACCEL_SM 15.4,21 r0 top locked
LOGO_GECKO "Comment" LOGO_GECKO_H4.0_SM 8,46.1 r0 top locked
LOGO_HUMID "Comment" LOGO_HUMID_3.2X3.2_SM 22,7.4 r0 top
LOGO_LIGHT "Comment" LOGO_LIGHT_SM 24.7,31.3 r0 top
LOGO_MAGNET "Comment" LOGO_MAGNET_SM 25.8,38.7 r90 top locked
LOGO_MIC_L "Comment" LOGO_MIC_L_SM 2.2,45.4 r0 top locked
LOGO_MIC_R "Comment" LOGO_MIC_R_SM 28.2,45.4 r0 top locked
LOGO_PRESSURE "Comment" LOGO_PRESSURE 24,16.1 r0 top locked
LOGO_QWIIC "Comment" LOGO_QWIIC_GM21_W7.0 4.1,18.5 r0 top locked
LOGO_SEGGER "LOGO_SEGGER_10.0X5.0_SM" LOGO_SEGGER_8.0X4.0_SM 6.8,6.8 r0 top
M900 "Comment" TESTJIGG_PCB4166_MECH2_SL 15.95,18.25 r0 top locked
M901 "2.2_MM" HOLE_2.2_NPL 5.6,15.7 r0 top locked
M902 "2.2_MM" HOLE_2.2_NPL 23.7,42 r0 top locked
P1 "MINI-SIMPLICITY" FTSH_105_01_L_DV_K 22.5,24.7 r90 top
P100 "U.FL" HRS_U.FL-R-SMT_123 2.6,39.4 r90 top
P102 "QWIIC_4P" WCON_WF1001A-WM04E-4 7.65,24.7 r270 top locked
P900 "USB_MICRO-B" FCI_10118194-000_MICRO_USB_B 15,0.4 r0 top locked
P901 "CR2032" BAT_HOLD_MPD_BK-912_CR2032_4166-1-2 15,7.5 r180 bottom locked
P902 "DF13C-2P-1.25V" HRS_DF13C-2P-1.25V 18.225,24.25 r90 bottom locked
Q200 "DMC2400UV" SOT563_L 22.3,21.1 r0 bottom
Q901 "SiA527DJ" POWERPAK_SC70-6_L 7.65,42.275 r90 bottom
Q902 "DMC2400UV" SOT563_L 5,42.325 r90 bottom
R1 "100R" R0201_L 21.25,39.425 r0 top
R6 "1R" R0201_L 10.975,29.975 r180 top
R100 "330K" R0201_L 16.5,33.7 r90 top
R102 "100K" R0201_L 17,28.25 r180 top
R103 "100K" R0201_L 17.55,22.75 r180 top
R107 "2K8" R0201_L 21.6,32.95 r0 top
R108 "2K8" R0201_L 21.9,29.4 r90 top
R109 "100K" R0201_L 22.5,29.4 r90 top
R112 "100K" R0201_L 27.15,40.775 r180 top
R114 "16K2" R0402_L 6.35,42.9 r270 top
R116 "205R" R0402_L 4.7,42.9 r90 top
R129 "14R" R0402_L 5.8,39.5 r0 top
R135 "698R" R0402_L 13.975,19.1 r270 top
R136 "910R" R0402_L 16.9,18.65 r0 top
R137 "2K32" R0402_L 16.9,19.55 r0 top
R140 "1M" R0201_L 22.7,3.2 r90 top
R141 "100R" R0201_L 29.2,2.1 r90 top
R143 "1M" R0201_L 7.7,3.2 r90 top
R144 "100R" R0201_L 1.2,2.1 r90 top
R150 "100K" R0201_L 1.3,46.05 r180 bottom
R157 "1R" R0201_L 28.525,45.6 r90 bottom
R158 "1R" R0201_L 2.2,45.75 r90 bottom
R206 "100R" R0402_L 24.4,20.25 r180 bottom
R207 "10K" R0402_L 24.4,21.125 r0 bottom
R208 "10K" R0402_L 22.1,19.7 r180 bottom
R209 "0R" R0402_L 24.4,19.375 r180 bottom
R210 "0R" R0402_L 24.4,22 r0 bottom
R212 "100R" R0402_L 24.4,18.5 r0 bottom
R901 "1K" R0201_L 12.025,20.55 r270 bottom
R903 "33R" R0402_L 6.8,20.7 r90 bottom
R904 "33R" R0402_L 5.925,20.7 r90 bottom
R905 "5K76" R0201_L 18.725,6.4 r90 top
R906 "330K" R0201_L 4.65,29.2 r0 bottom
R907 "10K" R0201_L 7.2,49.65 r0 bottom
R908 "180K" R0201_L 4.775,48.6 r270 bottom
R909 "110K" R0201_L 4.2,48.6 r90 bottom
R910 "4K7" R0201_L 22.8,30.625 r0 bottom
R911 "4K7" R0201_L 22.8,29.975 r0 bottom
R912 "10K" R0201_L 22.8,29.4 r0 bottom
R915 "470K" R0201_L 7.65,40.45 r90 bottom
R916 "10K" R0201_L 5.775,40.375 r180 bottom
R917 "1K" R0201_L 4.5,40.375 r180 bottom
R918 "330K" R0201_L 4.8,43.825 r180 bottom
R919 "470R" R0201_L 6.4,29.9 r90 bottom
R920 "470R" R0201_L 7.3,29.9 r90 bottom
R921 "470R" R0201_L 10.95,29.4 r180 bottom
R929 "1K" R0201_L 6.225,42.575 r90 bottom
R930 "1K" R0201_L 12.625,21.275 r270 bottom
R931 "1K" R0201_L 16.8,28.1 r0 bottom
R933 "4K7" R0201_L 6.225,43.775 r90 bottom
R934 "0R" R0201_L 4.801,40.068 r270 bottom
SW1 "PTS810" SW_CK_PTS810 20.6,36.4 r90 top
SW100 "PTS810" SW_CK_PTS810 26.3,2.2 r0 top
SW101 "PTS810" SW_CK_PTS810 4.1,2.2 r0 top
TP1 "TPJ_SMD" TP_1.0_SMD 24.5,27.8 r180 bottom
TP2 "TPJ_SMD" TP_1.0_SMD 26.8,40 r180 bottom
TP3 "TPJ_SMD" TP_1.0_SMD 20.8,17.8 r180 bottom
TP900 "TPJ_SMD" TP_1.0_SMD 5,38 r90 bottom
TP999 "PROTO_TH" PROTO_TH 4.65,2.5 r180 bottom
TPJ1 "TPJ_SMD" TP_1.0_SMD 15.95,18.25 r90 bottom locked
TPJ2 "TPJ_SMD" TP_1.0_SMD 16.3,34.38 r90 bottom locked
TPJ3 "TPJ_SMD" TP_1.0_SMD 15.9,20.8 r90 bottom locked
TPJ5 "TPJ_SMD" TP_1.0_SMD 13.75,29.2 r90 bottom locked
TPJ6 "TPJ_SMD" TP_1.0_SMD 17.22,31.57 r90 bottom locked
TPJ11 "TPJ_SMD" TP_1.0_SMD 24.8,24.25 r90 bottom locked
TPJ12 "TPJ_SMD" TP_1.0_SMD 24.15,34.95 r90 bottom locked
TPJ13 "TPJ_SMD" TP_1.0_SMD 22.8,22.7 r90 bottom locked
TPJ14 "TPJ_SMD" TP_1.0_SMD 24.55,29.7 r90 bottom locked
TPJ15 "TPJ_SMD" TP_1.0_SMD 24.55,32.3 r90 bottom locked
TPJ16 "TPJ_SMD" TP_1.0_SMD 22.45,18.25 r90 bottom locked
TPJ17 "TPJ_SMD" TP_1.0_SMD 13.75,26.6 r90 bottom locked
TPJ18 "TPJ_SMD" TP_1.0_SMD 6.35,18.92 r90 bottom
TPJ19 "TPJ_SMD" TP_1.0_SMD 4.2,17.9 r90 bottom locked
U1 "EFR32MG24A110F1536GM48" QFN48_M040_6.0X6.0_EP4.3X4.3_SL_EFR32MG24 11.5,36.8 r180 top locked
U101 "TS3A4751" QFN14_M040_2.0X2.0_TI_RUC 19.7,41.2 r90 bottom
U102 "TS3A4751" QFN14_M040_2.0X2.0_TI_RUC 21.4,36.8 r90 bottom
U103 "TS3A4751" QFN14_M040_2.0X2.0_TI_RUC 19.7,33.4 r90 bottom
U104 "ICM-20689" QFN24_M050_4.0X4.0_NO_EP_ICM-20689 15.4,25.5 r0 top locked
U105 "VEML6035" SENS_VISH_VEML6035 21.9,31.3 r90 top locked
U106 "BMP384" BOSCH_BMP384_LGA10_M050_2.0X2.0 24,19.1 r0 top
U107 "Si7210" SOT23-5_L 27.8,38.7 r90 top locked
U108 "Si7021" DFN6_3X3MM_SI7021 28,7.4 r90 top
U110 "MX25R3235F" WLCSP12_M035X040_1.99X2.23_MXIC 17.3,35.5 r270 top
U111 "ICS-43434" MIC_INVENSENSE_ICS-43434 28.2,49.1 r180 bottom locked
U112 "ICS-43434" MIC_INVENSENSE_ICS-43434 2.2,49.1 r180 bottom locked
U900 "EFM32GG12B410F1024GL120-A" BGA120_M050_7.0X7.0_SL_EFM32GG12 9.25,25.5 r270 bottom locked
U901 "MX25R8035F" BGA8_3-2-3_M040_1.24x1.75_WLCSP 4.75,27.2 r180 bottom locked
U902 "LP3982ILD-ADJ" LLP8_MA65_W3.0 6.425,47.75 r90 bottom
U903 "24AA024" TDFN8_M050_2.0X3.0_EP 20.075,29.725 r0 bottom locked
X1 "39.000_MHz" X_KDS_DSX211SH_2.0X1.65-4 16.65,39.3 r270 top locked
X2 "32.768_kHz" X_KDS_DST1610A_1610 15.4,33.35 r270 top
X900 "48_MHz" X_SSS_DSX211SH_2.05X1.65-4 14.6,24.6 r90 bottom

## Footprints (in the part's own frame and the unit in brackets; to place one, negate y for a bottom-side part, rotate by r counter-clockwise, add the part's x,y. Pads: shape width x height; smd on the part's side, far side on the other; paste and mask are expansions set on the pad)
ANT_JOH_2450AT18D0100 [mm] "Antenna, Johanson 2450AT18D0100"
  rrect5% 1x0.6 smd: 1(-1.5,-0.65) 2(1.5,-0.65) 3(1.5,0.65) 4(-1.5,0.65)
  silkscreen extent -1.6,-0.8 1.6,0.8, body extent -1.6,-0.8 1.6,0.8, height 1.41
BAT_HOLD_MPD_BK-912_CR2032_4166-1-2 [mil] "MPD Battery Holder BK-912 (for CR2032)"
  rrect20% 110x200 smd: 1(-430,0) 1(430,0)
  round 157.48 smd paste-295.67 mask-82.68: 2(0,0)
  silkscreen extent -449,-393 451,394, body extent -415,-311 417,291, height 175
BGA8_3-2-3_M040_1.24x1.75_WLCSP [mm] "BGA, 8 pin (170123)"
  round 0.21 smd mask+0.051: A1(-0.35,0.4) A3(0.35,0.4) B2(0,0.2) C1(-0.35,0) C3(0.35,0) D2(0,-0.2) E1(-0.35,-0.4) E3(0.35,-0.4)
  silkscreen extent -0.63,-0.89 0.63,0.88, body extent -0.63,-0.89 0.63,0.88, height 0.53
BGA120_M050_7.0X7.0_SL_EFM32GG12 [mm] "BGA, 120 Leads, Body 7.0x7.0mmx1,30mm, Pitch 0.50mm"
  round 0.2 smd mask+0.04: A1(-3,3) A2(-2.5,3) A3(-2,3) A4(-1.5,3) A5(-1,3) A6(-0.5,3) A7(0,3) A8(0.5,3) A9(1,3) A10(1.5,3) A11(2,3) A12(2.5,3) A13(3,3) B1(-3,2.5) B2(-2.5,2.5) B3(-2,2.5) B4(-1.5,2.5) B5(-1,2.5) B6(-0.5,2.5) B7(0,2.5) B8(0.5,2.5) B9(1,2.5) B10(1.5,2.5) B11(2,2.5) B12(2.5,2.5) B13(3,2.5) C1(-3,2) C2(-2.5,2) C3(-2,2) C4(-1.5,2) C5(-1,2) C6(-0.5,2) C7(0,2) C8(0.5,2) C9(1,2) C10(1.5,2) C11(2,2) C12(2.5,2) C13(3,2) D1(-3,1.5) D2(-2.5,1.5) D3(-2,1.5) D11(2,1.5) D12(2.5,1.5) D13(3,1.5) E1(-3,1) E2(-2.5,1) E3(-2,1) E11(2,1) E12(2.5,1) E13(3,1) F1(-3,0.5) F2(-2.5,0.5) F3(-2,0.5) F11(2,0.5) F12(2.5,0.5) F13(3,0.5) G1(-3,0) G2(-2.5,0) G3(-2,0) G11(2,0) G12(2.5,0) G13(3,0) H1(-3,-0.5) H2(-2.5,-0.5) H3(-2,-0.5) H11(2,-0.5) H12(2.5,-0.5) H13(3,-0.5) J1(-3,-1) J2(-2.5,-1) J3(-2,-1) J11(2,-1) J12(2.5,-1) J13(3,-1) K1(-3,-1.5) K2(-2.5,-1.5) K3(-2,-1.5) K11(2,-1.5) K12(2.5,-1.5) K13(3,-1.5) L1(-3,-2) L2(-2.5,-2) L3(-2,-2) L4(-1.5,-2) L5(-1,-2) L6(-0.5,-2) L7(0,-2) L8(0.5,-2) L9(1,-2) L10(1.5,-2) L11(2,-2) L12(2.5,-2) L13(3,-2) M1(-3,-2.5) M2(-2.5,-2.5) M3(-2,-2.5) M4(-1.5,-2.5) M5(-1,-2.5) M6(-0.5,-2.5) M7(0,-2.5) M8(0.5,-2.5) M9(1,-2.5) M10(1.5,-2.5) M11(2,-2.5) M12(2.5,-2.5) M13(3,-2.5) N1(-3,-3) N2(-2.5,-3) N3(-2,-3) N4(-1.5,-3) N5(-1,-3) N6(-0.5,-3) N7(0,-3) N8(0.5,-3) N9(1,-3) N10(1.5,-3) N11(2,-3) N12(2.5,-3) N13(3,-3)
  silkscreen extent -3.5,-3.5 3.5,3.5, body extent -3.5,-3.5 3.5,3.5, height 1.3
BOSCH_BMP384_LGA10_M050_2.0X2.0 [mm] "(210607)"
  rrect10% 0.27x0.285 smd paste-0.025 mask+0.05: 1(0.25,0.757) 2(-0.25,0.757) 6(-0.25,-0.757) 7(0.25,-0.757)
  rrect10% 0.285x0.27 smd paste-0.025 mask+0.05: 3(-0.757,0.5) 4(-0.757,0) 5(-0.757,-0.5) 8(0.757,-0.5) 9(0.757,0) 10(0.757,0.5)
  silkscreen extent -1,-1 1,1, body extent -1,-1 1,1, height 1.01
C0201_L [mm] "Capacitor"
  rrect25% 0.36x0.32 smd: 1(-0.275,0) 2(0.275,0)
  silkscreen extent -0.29,-0.15 0.29,0.15, body extent -0.32,-0.13 0.32,0.13, height 0.3
C0402_L [mm] "Chip Capacitor, 2-Leads, Body 1.0x0.5mm, IPC High Density (170201)"
  rrect20% 0.6x0.5 smd mask+0.051: 1(-0.45,0) 2(0.45,0)
  silkscreen extent -0.5,-0.25 0.5,0.25, body extent -0.5,-0.25 0.5,0.25, height 0.6
C0603_L [mm] "Capacitor, 0603, High Density (C) (170201)"
  rrect25% 0.8x0.85 smd: 1(-0.7,0) 2(0.7,0)
  silkscreen extent -0.88,-0.48 0.87,0.48, body extent -0.88,-0.48 0.87,0.48, height 0.95
C0805_L [mm] "Capacitor, 0805"
  rrect25% 0.95x1.35 smd: 1(-0.8,0) 2(0.8,0)
  silkscreen extent -1.12,-0.72 1.1,0.72, body extent -1.1,-0.72 1.1,0.72, height 1.45
COIL_0201_L [mm] "Inductor, 0201, High Density (C)"
  rrect10% 0.37x0.32 smd: 1(-0.27,0) 2(0.27,0)
  silkscreen extent -0.32,-0.17 0.32,0.17, body extent -0.32,-0.17 0.32,0.17, height 0.33
COIL_0402_L [mm] "COIL_0402_L (3D from Wurth)"
  rrect20% 0.55x0.5 smd mask+0.051: 1(-0.525,0) 2(0.525,0)
  silkscreen extent -0.5,-0.25 0.5,0.25, body extent -0.5,-0.25 0.5,0.25, height 0.5
COIL_0603_L [mm] "COIL 0603_L (= L0603_0.8_L)"
  rrect10% 0.75x0.88 smd: 1(-0.725,0) 2(0.725,0)
  silkscreen extent -0.8,-0.4 0.8,0.4, body extent -0.8,-0.4 0.8,0.4, height 0.8
COIL_MUR_BLM03_0201 [mm] "Inductor, 0201, High Density (C)"
  rrect10% 0.37x0.32 smd: 1(-0.27,0) 2(0.27,0)
  silkscreen extent -0.32,-0.17 0.32,0.17, body extent -0.32,-0.17 0.32,0.17, height 0.33
DFN6_3X3MM_SI7021 [mm]
  rrect20% 0.85x0.45 smd: 1(-1.45,1) 2(-1.45,0) 3(-1.45,-1) 4(1.45,-1) 5(1.45,0) 6(1.45,1)
  rrect20% 1.6x2.5 smd: 7(0,0)
  silkscreen extent -1.5,-1.5 1.5,1.5, body extent -1.5,-1.5 1.5,1.5, height 1.22
DO220AA [mm] "Diode DO220AA (DO-220AA) (= SMP) (Vishay) (170512)"
  rrect20% 2.67x2.3 smd: 1(-0.85,0)
  rrect20% 1x1.27 smd: 2(1.8,0)
  silkscreen extent -2,-1.09 2.1,1.09, body extent -2,-1.09 2.1,1.09, height 1.15
FCI_10118194-000_MICRO_USB_B [mm] "Amphenol FCI, 10118194-000XLF, Micro USB Type B"
  rrect20% 0.4x1.35 smd mask+0.076: 1(-1.305,4.15) 2(-0.655,4.15) 3(-0.005,4.15) 4(0.645,4.15) 5(1.295,4.15)
  oval 1.25x0.95 hole 0.55 slot 0.85 at 0 deg: 6(-2.505,4.15) 7(2.495,4.15)
  oval 0.9x1.55 hole 0.5 slot 1.15 at 90 deg paste+0: 8(-3.505,1.45) 9(3.495,1.45)
  rrect5% 1.5x1.55 smd: 10(-1.005,1.45) 11(0.995,1.45)
  Top Layer region: 3.476,0.676 2.32,0.676 2.296,0.7 2.298,2.206 2.32,2.228 3.472,2.228 3.711,2.164 3.886,1.989 3.95,1.75 3.95,1.75 3.95,1.15 3.886,0.913 3.713,0.74 3.476,0.676
  Top Layer region: -3.501,0.676 -2.33,0.676 -2.306,0.7 -2.308,2.206 -2.33,2.228 -3.497,2.228 -3.724,2.167 -3.889,2.001 -3.95,1.775 -3.95,1.775 -3.95,1.125 -3.916,0.953 -3.818,0.807 -3.673,0.71 -3.501,0.676
  silkscreen extent -4.03,-1.22 4.02,4.95, body extent -4.05,-1.18 4,4.4, height 3.12
FTSH_105_01_L_DV_K [mm]
  rrect20% 0.74x2.55 smd mask+0.051: 1(-2.54,-2.035) 2(-2.54,2.035) 3(-1.27,-2.035) 4(-1.27,2.035) 5(0,-2.035) 6(0,2.035) 7(1.27,-2.035) 8(1.27,2.035) 9(2.54,-2.035) 10(2.54,2.035)
  silkscreen extent -3.17,-1.72 3.17,1.72, body extent -3.23,-1.76 3.22,1.77, height 5.56
HDR_M254-1X10_PLUS_1X10_NO_3D [mm] "No 3D model for this component"
  round 1.6 hole 1: 1(0,-25.4) 2(0,0) 3(2.54,-25.4) 4(2.54,0) 5(5.08,-25.4) 6(5.08,0) 7(7.62,-25.4) 8(7.62,0) 9(10.16,-25.4) 10(10.16,0) 11(12.7,-25.4) 12(12.7,0) 13(15.24,-25.4) 14(15.24,0) 15(17.78,-25.4) 16(17.78,0) 17(20.32,-25.4) 18(20.32,0) 19(22.86,-25.4) 20(22.86,0)
  silkscreen extent -1.4,-26.67 24.13,1.27
HOLE_2.2_NPL [mm]
  round 0 hole 2.2 unplated mask+0.1: 1(0,0)
  silkscreen extent -2,-2 2,2
HRS_DF13C-2P-1.25V [mm]
  rrect20% 0.7x1.8 smd: 1(-0.625,-1.4) 2(0.625,-1.4)
  rrect20% 1.6x2.2 smd: 3(2.975,1.4) 4(-2.975,1.4)
  Mechanical 13 keep-out region: -0.975,1.97 0.975,1.97 0.975,-0.4 -0.975,-0.4
  silkscreen extent -3.57,-1.82 3.57,3.2, body extent -3.66,-1.85 3.65,3.23, height 4.8
HRS_U.FL-R-SMT_123 [mm] "COAX_HIROSE_U.FL_CL331-0471 (170228)"
  rrect20% 1.05x1.1 smd mask+0.051: 1(0,-1.6)
  rrect20% 1.05x2.25 smd mask+0.051: 2(1.5,0) 3(-1.5,0)
  Top Layer pour cut-out: 0.85,-0.9 -0.85,-0.9 -0.85,-0.9 -0.85,1.2 0.85,1.2 0.85,1.2
  silkscreen extent -1.5,-1.55 1.5,1.55, body extent -1.3,-1.3 1.3,1.55, height 0.9
LED_0402_CAT2 [mm] "(200921)"
  rrect10% 0.45x0.6 smd: 1(-0.45,0) 2(0.45,0)
  silkscreen extent -0.55,-0.33 0.55,0.33, body extent -0.55,-0.33 0.55,0.33, height 0.25
LED_LUMEX_SML-LX0404-4 [mm] "LED, LUMEX, SML LX0404 1.0x1.0x0.25 NB! Pin numbering"
  rrect25% 0.45x0.45 smd mask+0.05: 1(-0.425,-0.425) 2(-0.425,0.425) 3(0.425,0.425) 4(0.425,-0.425)
  silkscreen extent -0.5,-0.5 0.5,0.5, body extent -0.5,-0.5 0.5,0.5, height 0.31
LLP8_MA65_W3.0 [mm]
  rrect20% 0.5x0.25 smd: 1(-1.15,0.75) 2(-1.15,0.25) 3(-1.15,-0.25) 4(-1.15,-0.75) 5(1.15,-0.75) 6(1.15,-0.25) 7(1.15,0.25) 8(1.15,0.75)
  rrect20% 1.2x1.5 smd: 9(0,0)
  silkscreen extent -1.55,-1.3 1.55,1.3, body extent -1.55,-1.3 1.55,1.3, height 0.8
LOGO_ACCEL_SM [mm] "(210603)"
LOGO_GECKO_H4.0_SM [mm] "Silicon Labs, Gecko logo"
LOGO_HUMID_3.2X3.2_SM [mm] "(210603)"
LOGO_LIGHT_SM [mm] "(210603)"
LOGO_MAGNET_SM [mm] "(210603)"
LOGO_MIC_L_SM [mm] "(210603)"
LOGO_MIC_R_SM [mm] "(210603)"
LOGO_PRESSURE [mm] "(210607)"
LOGO_QWIIC_GM21_W7.0 [mm] "Logo QWIIC GTO width 7.0 (200625)"
  silkscreen extent 0,0 7.11,2.22
LOGO_SEGGER_8.0X4.0_SM [mil] "(210607)"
